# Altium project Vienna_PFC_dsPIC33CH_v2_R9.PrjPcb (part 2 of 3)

## Sheet Vienna_PFC_GateDriver.SchDoc
size D; DocumentNumber: 4; SheetNumber: 4; SheetTotal: 11
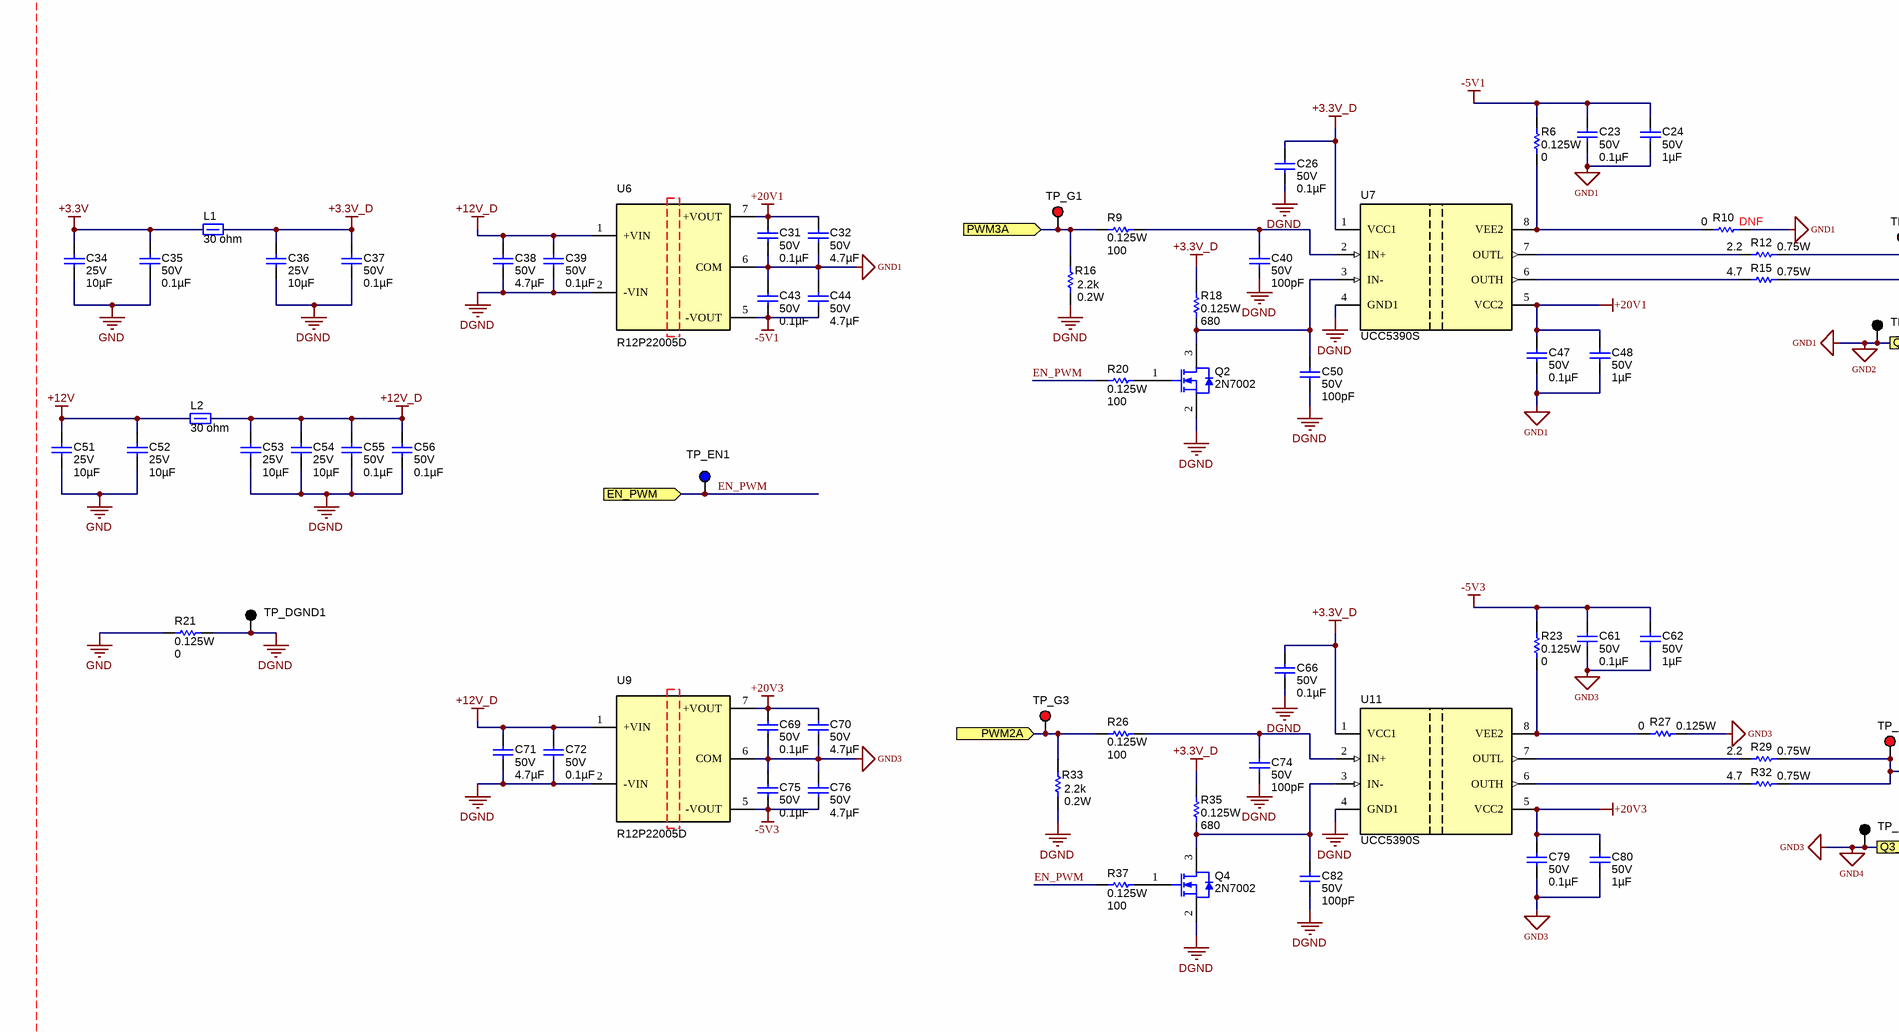
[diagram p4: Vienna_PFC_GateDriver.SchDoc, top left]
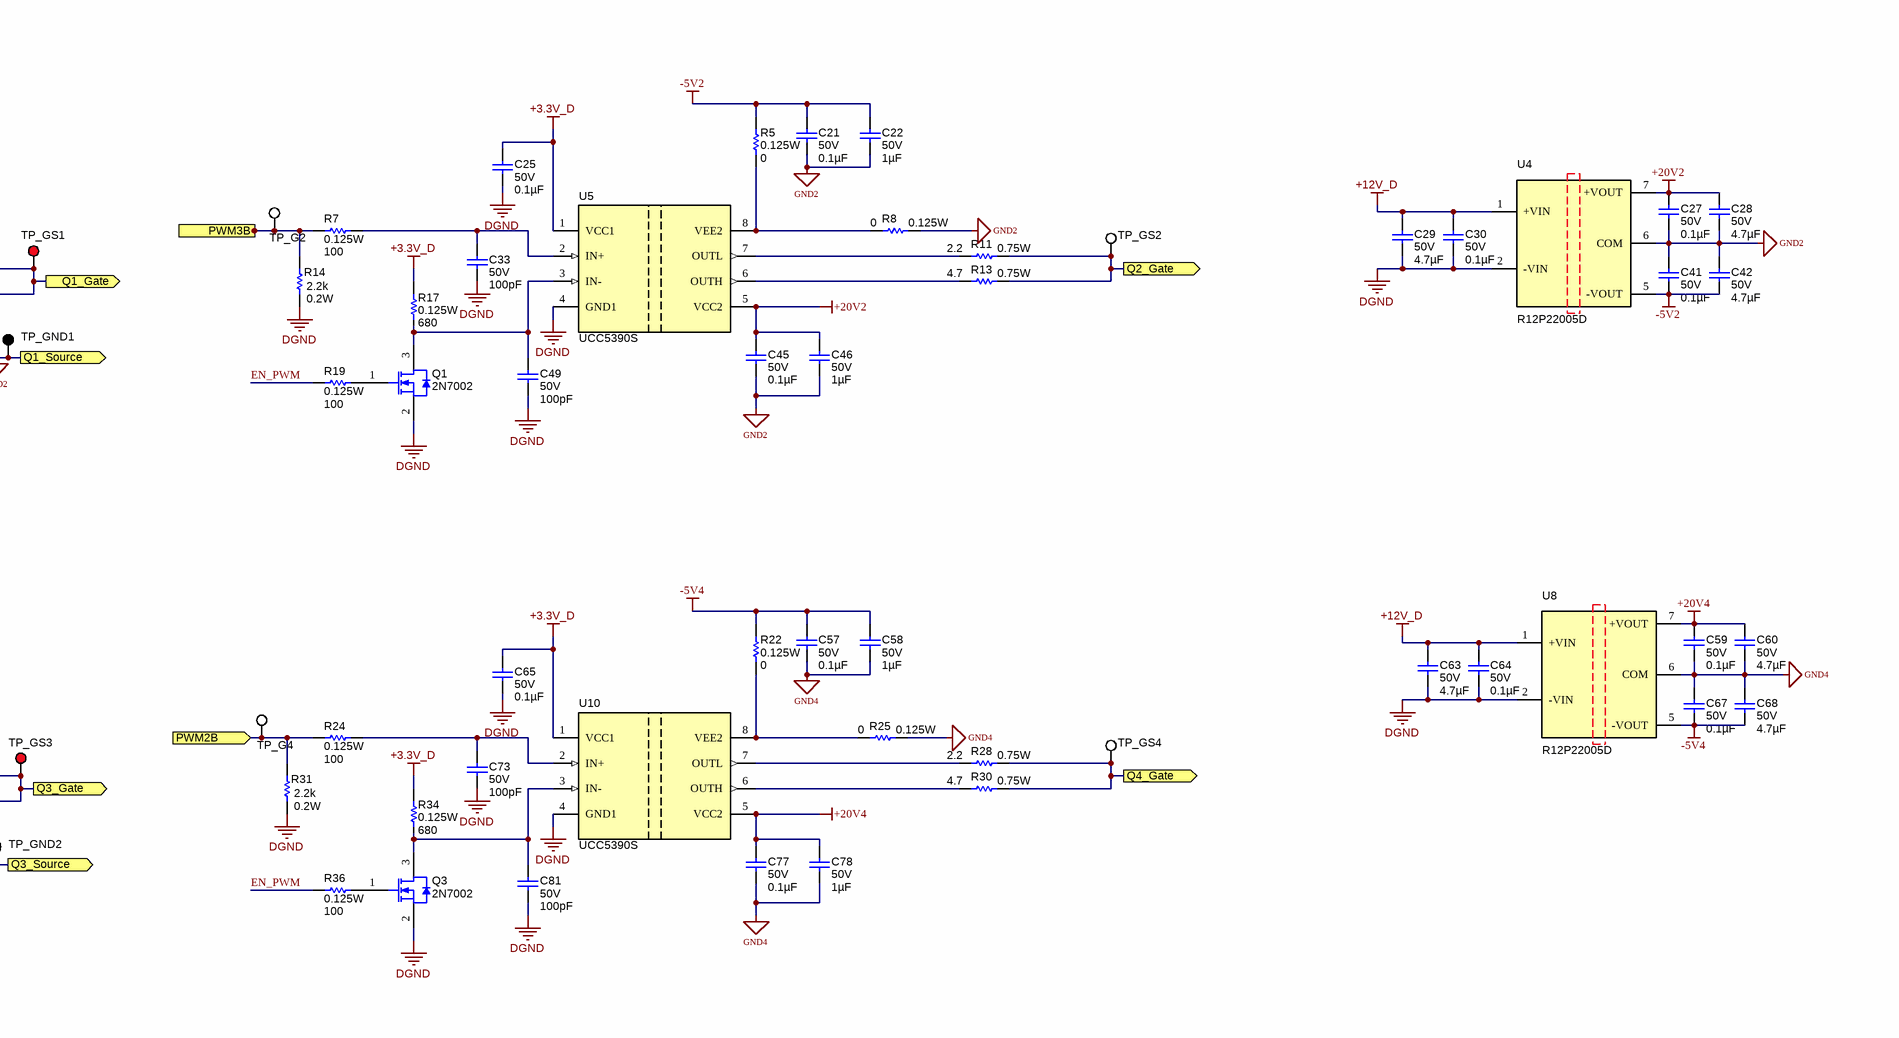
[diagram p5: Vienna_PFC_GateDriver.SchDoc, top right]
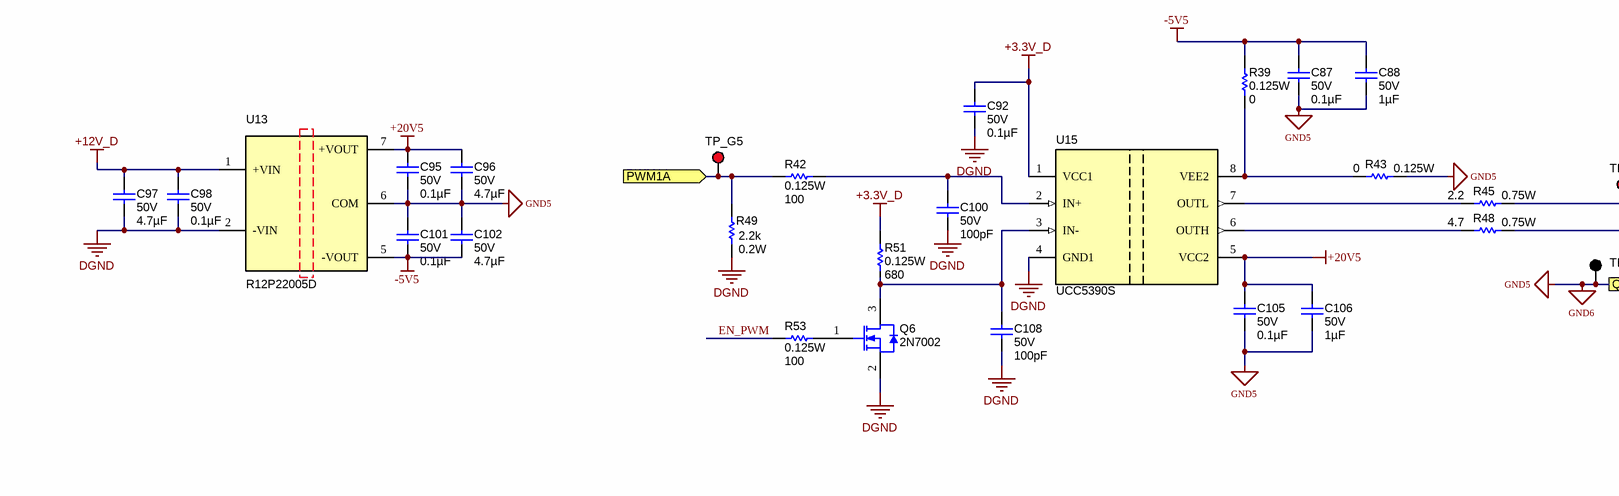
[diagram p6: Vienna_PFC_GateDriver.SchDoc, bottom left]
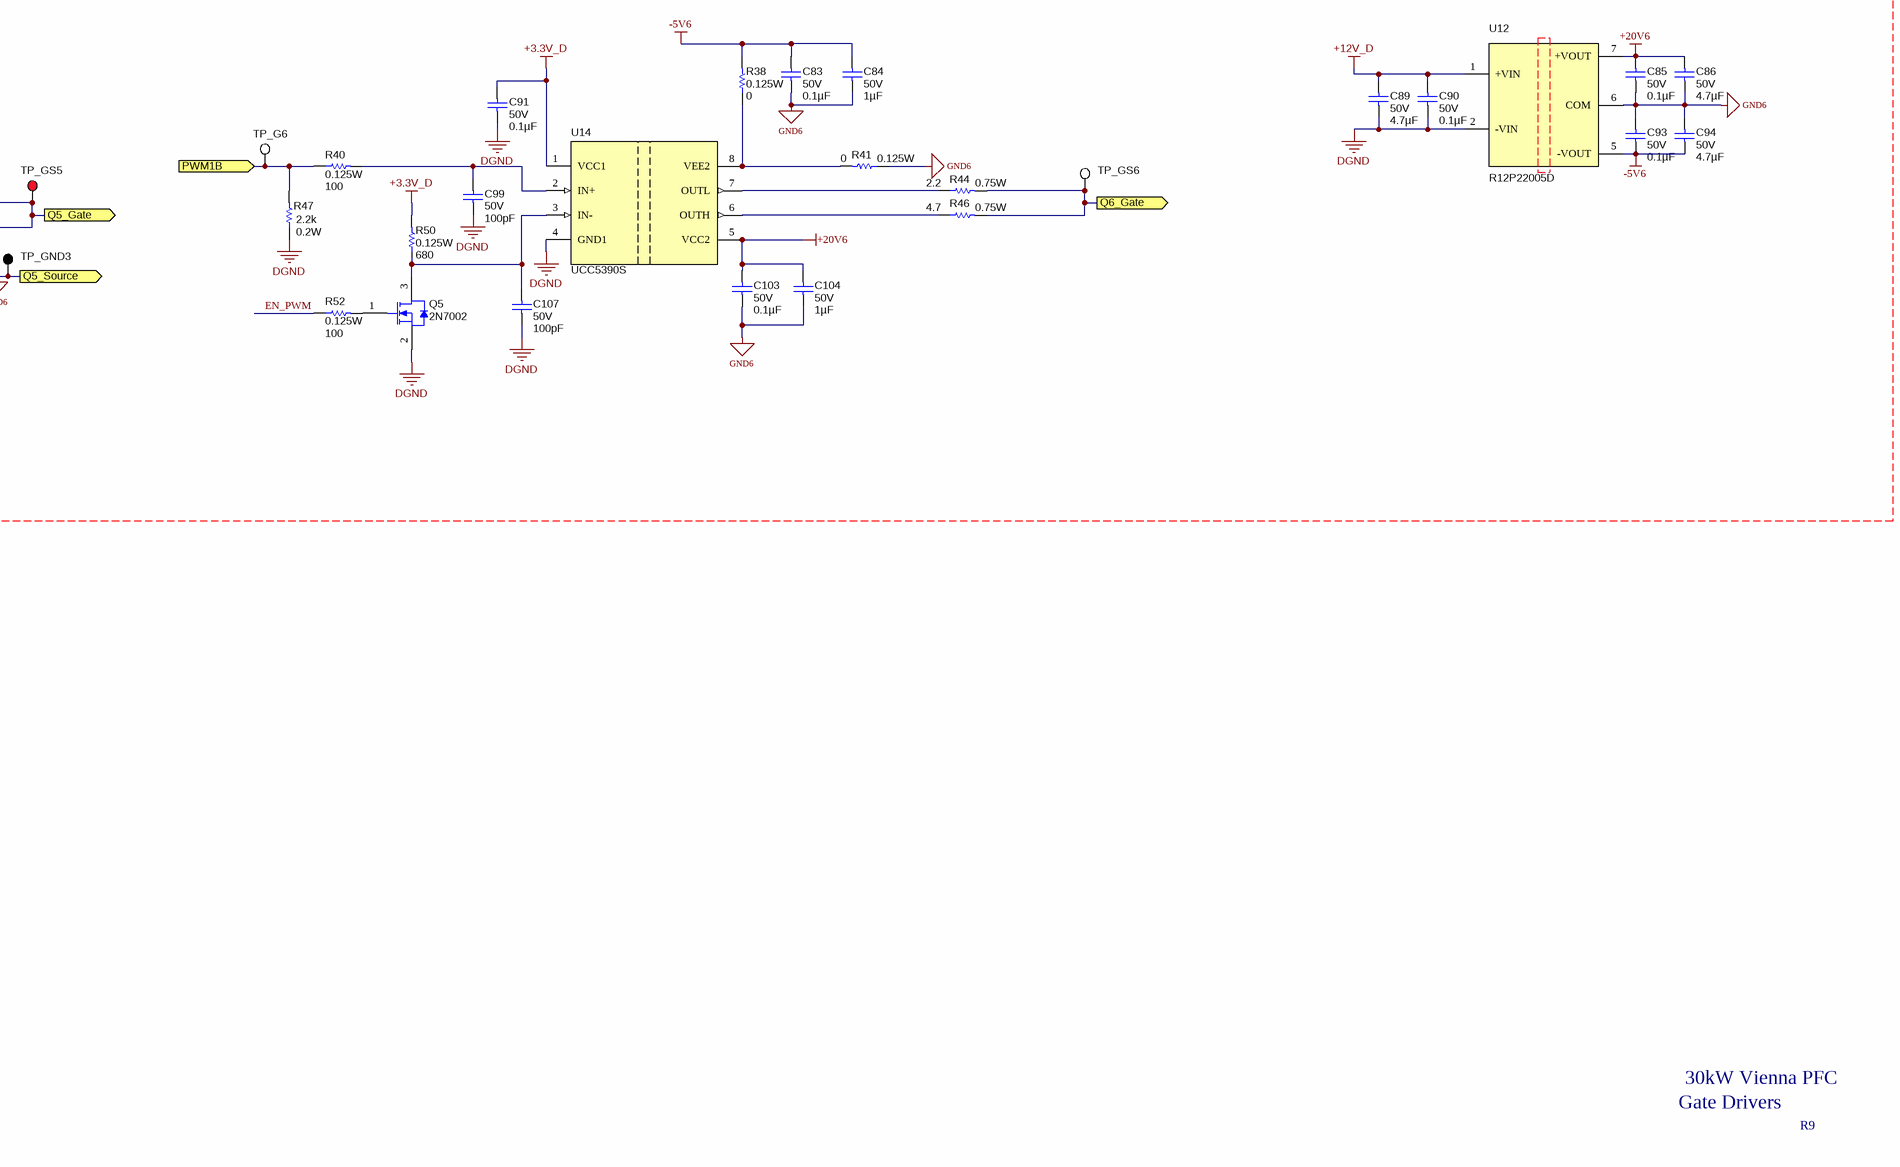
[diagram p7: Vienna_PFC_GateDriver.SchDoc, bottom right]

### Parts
(Parts that share a designator on the sheet are numbered #1, #2 ... from top to bottom, then left to right.)
?#5  (no value)  (graphical)
C21  VDC_V: 50V  ValueDisplayed: 0.1µF  [0805_HV]  (hidden comment: C0805C104J5RACTU)
C22  VDC_V: 50V  ValueDisplayed: 1µF  [0805_HV]  (hidden comment: C0805C105K5RACTU)
C23  VDC_V: 50V  ValueDisplayed: 0.1µF  [0805_HV]  (hidden comment: C0805C104J5RACTU)
C24  VDC_V: 50V  ValueDisplayed: 1µF  [0805_HV]  (hidden comment: C0805C105K5RACTU)
C25  VDC_V: 50V  ValueDisplayed: 0.1µF  [0805_HV]  (hidden comment: C0805C104J5RACTU)
C26  VDC_V: 50V  ValueDisplayed: 0.1µF  [0805_HV]  (hidden comment: C0805C104J5RACTU)
C27  VDC_V: 50V  ValueDisplayed: 0.1µF  [0805_HV]  (hidden comment: C0805C104J5RACTU)
C28  VDC_V: 50V  ValueDisplayed: 4.7µF  [0805_HV]  (hidden comment: C2012X5R1H475K125AB)
C29  VDC_V: 50V  ValueDisplayed: 4.7µF  [0805_HV]  (hidden comment: C2012X5R1H475K125AB)
C30  VDC_V: 50V  ValueDisplayed: 0.1µF  [0805_HV]  (hidden comment: C0805C104J5RACTU)
C31  VDC_V: 50V  ValueDisplayed: 0.1µF  [0805_HV]  (hidden comment: C0805C104J5RACTU)
C32  VDC_V: 50V  ValueDisplayed: 4.7µF  [0805_HV]  (hidden comment: C2012X5R1H475K125AB)
C33  VDC_V: 50V  ValueDisplayed: 100pF  [0805_HV]  (hidden comment: C0805C101J5RACTU)
C34  VDC_V: 25V  ValueDisplayed: 10µF  [1206_190]  (hidden comment: C1206C106K3RACAUTO)
C35  VDC_V: 50V  ValueDisplayed: 0.1µF  [0805_HV]  (hidden comment: C0805C104J5RACTU)
C36  VDC_V: 25V  ValueDisplayed: 10µF  [1206_190]  (hidden comment: C1206C106K3RACAUTO)
C37  VDC_V: 50V  ValueDisplayed: 0.1µF  [0805_HV]  (hidden comment: C0805C104J5RACTU)
C38  VDC_V: 50V  ValueDisplayed: 4.7µF  [0805_HV]  (hidden comment: C2012X5R1H475K125AB)
C39  VDC_V: 50V  ValueDisplayed: 0.1µF  [0805_HV]  (hidden comment: C0805C104J5RACTU)
C40  VDC_V: 50V  ValueDisplayed: 100pF  [0805_HV]  (hidden comment: C0805C101J5RACTU)
C41  VDC_V: 50V  ValueDisplayed: 0.1µF  [0805_HV]  (hidden comment: C0805C104J5RACTU)
C42  VDC_V: 50V  ValueDisplayed: 4.7µF  [0805_HV]  (hidden comment: C2012X5R1H475K125AB)
C43  VDC_V: 50V  ValueDisplayed: 0.1µF  [0805_HV]  (hidden comment: C0805C104J5RACTU)
C44  VDC_V: 50V  ValueDisplayed: 4.7µF  [0805_HV]  (hidden comment: C2012X5R1H475K125AB)
C45  VDC_V: 50V  ValueDisplayed: 0.1µF  [0805_HV]  (hidden comment: C0805C104J5RACTU)
C46  VDC_V: 50V  ValueDisplayed: 1µF  [0805_HV]  (hidden comment: C0805C105K5RACTU)
C47  VDC_V: 50V  ValueDisplayed: 0.1µF  [0805_HV]  (hidden comment: C0805C104J5RACTU)
C48  VDC_V: 50V  ValueDisplayed: 1µF  [0805_HV]  (hidden comment: C0805C105K5RACTU)
C49  VDC_V: 50V  ValueDisplayed: 100pF  [0805_HV]  (hidden comment: C0805C101J5RACTU)
C50  VDC_V: 50V  ValueDisplayed: 100pF  [0805_HV]  (hidden comment: C0805C101J5RACTU)
C51  VDC_V: 25V  ValueDisplayed: 10µF  [1206_190]  (hidden comment: C1206C106K3RACAUTO)
C52  VDC_V: 25V  ValueDisplayed: 10µF  [1206_190]  (hidden comment: C1206C106K3RACAUTO)
C53  VDC_V: 25V  ValueDisplayed: 10µF  [1206_190]  (hidden comment: C1206C106K3RACAUTO)
C54  VDC_V: 25V  ValueDisplayed: 10µF  [1206_190]  (hidden comment: C1206C106K3RACAUTO)
C55  VDC_V: 50V  ValueDisplayed: 0.1µF  [0805_HV]  (hidden comment: C0805C104J5RACTU)
C56  VDC_V: 50V  ValueDisplayed: 0.1µF  [0805_HV]  (hidden comment: C0805C104J5RACTU)
C57  VDC_V: 50V  ValueDisplayed: 0.1µF  [0805_HV]  (hidden comment: C0805C104J5RACTU)
C58  VDC_V: 50V  ValueDisplayed: 1µF  [0805_HV]  (hidden comment: C0805C105K5RACTU)
C59  VDC_V: 50V  ValueDisplayed: 0.1µF  [0805_HV]  (hidden comment: C0805C104J5RACTU)
C60  VDC_V: 50V  ValueDisplayed: 4.7µF  [0805_HV]  (hidden comment: C2012X5R1H475K125AB)
C61  VDC_V: 50V  ValueDisplayed: 0.1µF  [0805_HV]  (hidden comment: C0805C104J5RACTU)
C62  VDC_V: 50V  ValueDisplayed: 1µF  [0805_HV]  (hidden comment: C0805C105K5RACTU)
C63  VDC_V: 50V  ValueDisplayed: 4.7µF  [0805_HV]  (hidden comment: C2012X5R1H475K125AB)
C64  VDC_V: 50V  ValueDisplayed: 0.1µF  [0805_HV]  (hidden comment: C0805C104J5RACTU)
C65  VDC_V: 50V  ValueDisplayed: 0.1µF  [0805_HV]  (hidden comment: C0805C104J5RACTU)
C66  VDC_V: 50V  ValueDisplayed: 0.1µF  [0805_HV]  (hidden comment: C0805C104J5RACTU)
C67  VDC_V: 50V  ValueDisplayed: 0.1µF  [0805_HV]  (hidden comment: C0805C104J5RACTU)
C68  VDC_V: 50V  ValueDisplayed: 4.7µF  [0805_HV]  (hidden comment: C2012X5R1H475K125AB)
C69  VDC_V: 50V  ValueDisplayed: 0.1µF  [0805_HV]  (hidden comment: C0805C104J5RACTU)
C70  VDC_V: 50V  ValueDisplayed: 4.7µF  [0805_HV]  (hidden comment: C2012X5R1H475K125AB)
C71  VDC_V: 50V  ValueDisplayed: 4.7µF  [0805_HV]  (hidden comment: C2012X5R1H475K125AB)
C72  VDC_V: 50V  ValueDisplayed: 0.1µF  [0805_HV]  (hidden comment: C0805C104J5RACTU)
C73  VDC_V: 50V  ValueDisplayed: 100pF  [0805_HV]  (hidden comment: C0805C101J5RACTU)
C74  VDC_V: 50V  ValueDisplayed: 100pF  [0805_HV]  (hidden comment: C0805C101J5RACTU)
C75  VDC_V: 50V  ValueDisplayed: 0.1µF  [0805_HV]  (hidden comment: C0805C104J5RACTU)
C76  VDC_V: 50V  ValueDisplayed: 4.7µF  [0805_HV]  (hidden comment: C2012X5R1H475K125AB)
C77  VDC_V: 50V  ValueDisplayed: 0.1µF  [0805_HV]  (hidden comment: C0805C104J5RACTU)
C78  VDC_V: 50V  ValueDisplayed: 1µF  [0805_HV]  (hidden comment: C0805C105K5RACTU)
C79  VDC_V: 50V  ValueDisplayed: 0.1µF  [0805_HV]  (hidden comment: C0805C104J5RACTU)
C80  VDC_V: 50V  ValueDisplayed: 1µF  [0805_HV]  (hidden comment: C0805C105K5RACTU)
C81  VDC_V: 50V  ValueDisplayed: 100pF  [0805_HV]  (hidden comment: C0805C101J5RACTU)
C82  VDC_V: 50V  ValueDisplayed: 100pF  [0805_HV]  (hidden comment: C0805C101J5RACTU)
C83  VDC_V: 50V  ValueDisplayed: 0.1µF  [0805_HV]  (hidden comment: C0805C104J5RACTU)
C84  VDC_V: 50V  ValueDisplayed: 1µF  [0805_HV]  (hidden comment: C0805C105K5RACTU)
C85  VDC_V: 50V  ValueDisplayed: 0.1µF  [0805_HV]  (hidden comment: C0805C104J5RACTU)
C86  VDC_V: 50V  ValueDisplayed: 4.7µF  [0805_HV]  (hidden comment: C2012X5R1H475K125AB)
C87  VDC_V: 50V  ValueDisplayed: 0.1µF  [0805_HV]  (hidden comment: C0805C104J5RACTU)
C88  VDC_V: 50V  ValueDisplayed: 1µF  [0805_HV]  (hidden comment: C0805C105K5RACTU)
C89  VDC_V: 50V  ValueDisplayed: 4.7µF  [0805_HV]  (hidden comment: C2012X5R1H475K125AB)
C90  VDC_V: 50V  ValueDisplayed: 0.1µF  [0805_HV]  (hidden comment: C0805C104J5RACTU)
C91  VDC_V: 50V  ValueDisplayed: 0.1µF  [0805_HV]  (hidden comment: C0805C104J5RACTU)
C92  VDC_V: 50V  ValueDisplayed: 0.1µF  [0805_HV]  (hidden comment: C0805C104J5RACTU)
C93  VDC_V: 50V  ValueDisplayed: 0.1µF  [0805_HV]  (hidden comment: C0805C104J5RACTU)
C94  VDC_V: 50V  ValueDisplayed: 4.7µF  [0805_HV]  (hidden comment: C2012X5R1H475K125AB)
C95  VDC_V: 50V  ValueDisplayed: 0.1µF  [0805_HV]  (hidden comment: C0805C104J5RACTU)
C96  VDC_V: 50V  ValueDisplayed: 4.7µF  [0805_HV]  (hidden comment: C2012X5R1H475K125AB)
C97  VDC_V: 50V  ValueDisplayed: 4.7µF  [0805_HV]  (hidden comment: C2012X5R1H475K125AB)
C98  VDC_V: 50V  ValueDisplayed: 0.1µF  [0805_HV]  (hidden comment: C0805C104J5RACTU)
C99  VDC_V: 50V  ValueDisplayed: 100pF  [0805_HV]  (hidden comment: C0805C101J5RACTU)
C100  VDC_V: 50V  ValueDisplayed: 100pF  [0805_HV]  (hidden comment: C0805C101J5RACTU)
C101  VDC_V: 50V  ValueDisplayed: 0.1µF  [0805_HV]  (hidden comment: C0805C104J5RACTU)
C102  VDC_V: 50V  ValueDisplayed: 4.7µF  [0805_HV]  (hidden comment: C2012X5R1H475K125AB)
C103  VDC_V: 50V  ValueDisplayed: 0.1µF  [0805_HV]  (hidden comment: C0805C104J5RACTU)
C104  VDC_V: 50V  ValueDisplayed: 1µF  [0805_HV]  (hidden comment: C0805C105K5RACTU)
C105  VDC_V: 50V  ValueDisplayed: 0.1µF  [0805_HV]  (hidden comment: C0805C104J5RACTU)
C106  VDC_V: 50V  ValueDisplayed: 1µF  [0805_HV]  (hidden comment: C0805C105K5RACTU)
C107  VDC_V: 50V  ValueDisplayed: 100pF  [0805_HV]  (hidden comment: C0805C101J5RACTU)
C108  VDC_V: 50V  ValueDisplayed: 100pF  [0805_HV]  (hidden comment: C0805C101J5RACTU)
L1  value 30 ohm  [0805_HV]  (hidden comment: MPZ2012S300AT000)
L2  value 30 ohm  [0805_HV]  (hidden comment: MPZ2012S300AT000)
Q1  2N7002  [SOT-23]
Q2  2N7002  [SOT-23]
Q3  2N7002  [SOT-23]
Q4  2N7002  [SOT-23]
Q5  2N7002  [SOT-23]
Q6  2N7002  [SOT-23]
R5  Value2: 0.125W  ValueDisplayed: 0  [0805_HV]  (hidden comment: CRCW08050000Z0EA)
R6  Value2: 0.125W  ValueDisplayed: 0  [0805_HV]  (hidden comment: CRCW08050000Z0EA)
R7  Value2: 0.125W  ValueDisplayed: 100  [0805_HV]  (hidden comment: CRCW0805100RFKEAC)
R8  Value2: 0.125W  ValueDisplayed: 0  [0805_HV]  (hidden comment: CRCW08050000Z0EA)
R9  Value2: 0.125W  ValueDisplayed: 100  [0805_HV]  (hidden comment: CRCW0805100RFKEAC)
R10  Value2: DNF  ValueDisplayed: 0  [0805_HV]  (hidden comment: CRCW08050000Z0EA)
R11  Value2: 0.75W  ValueDisplayed: 2.2  [1206_190]  (hidden comment: CRCW12064R70FKEAHP)
R12  Value2: 0.75W  ValueDisplayed: 2.2  [1206_190]  (hidden comment: CRCW12064R70FKEAHP)
R13  Value2: 0.75W  ValueDisplayed: 4.7  [1206_190]  (hidden comment: CRCW12062R20FKEAHP)
R14  value 2.2k  Power_W: 0.2W  [0805_HV]  (hidden comment: TNPW08052K20BEEA)
R15  Value2: 0.75W  ValueDisplayed: 4.7  [1206_190]  (hidden comment: CRCW12062R20FKEAHP)
R16  value 2.2k  Power_W: 0.2W  [0805_HV]  (hidden comment: TNPW08052K20BEEA)
R17  Value2: 0.125W  ValueDisplayed: 680  [0805_HV]  (hidden comment: CRCW0805680RFKEA)
R18  Value2: 0.125W  ValueDisplayed: 680  [0805_HV]  (hidden comment: CRCW0805680RFKEA)
R19  Value2: 0.125W  ValueDisplayed: 100  [0805_HV]  (hidden comment: CRCW0805100RFKEAC)
R20  Value2: 0.125W  ValueDisplayed: 100  [0805_HV]  (hidden comment: CRCW0805100RFKEAC)
R21  Value2: 0.125W  ValueDisplayed: 0  [0805_HV]  (hidden comment: CRCW08050000Z0EA)
R22  Value2: 0.125W  ValueDisplayed: 0  [0805_HV]  (hidden comment: CRCW08050000Z0EA)
R23  Value2: 0.125W  ValueDisplayed: 0  [0805_HV]  (hidden comment: CRCW08050000Z0EA)
R24  Value2: 0.125W  ValueDisplayed: 100  [0805_HV]  (hidden comment: CRCW0805100RFKEAC)
R25  Value2: 0.125W  ValueDisplayed: 0  [0805_HV]  (hidden comment: CRCW08050000Z0EA)
R26  Value2: 0.125W  ValueDisplayed: 100  [0805_HV]  (hidden comment: CRCW0805100RFKEAC)
R27  Value2: 0.125W  ValueDisplayed: 0  [0805_HV]  (hidden comment: CRCW08050000Z0EA)
R28  Value2: 0.75W  ValueDisplayed: 2.2  [1206_190]  (hidden comment: CRCW12064R70FKEAHP)
R29  Value2: 0.75W  ValueDisplayed: 2.2  [1206_190]  (hidden comment: CRCW12064R70FKEAHP)
R30  Value2: 0.75W  ValueDisplayed: 4.7  [1206_190]  (hidden comment: CRCW12062R20FKEAHP)
R31  value 2.2k  Power_W: 0.2W  [0805_HV]  (hidden comment: TNPW08052K20BEEA)
R32  Value2: 0.75W  ValueDisplayed: 4.7  [1206_190]  (hidden comment: CRCW12062R20FKEAHP)
R33  value 2.2k  Power_W: 0.2W  [0805_HV]  (hidden comment: TNPW08052K20BEEA)
R34  Value2: 0.125W  ValueDisplayed: 680  [0805_HV]  (hidden comment: CRCW0805680RFKEA)
R35  Value2: 0.125W  ValueDisplayed: 680  [0805_HV]  (hidden comment: CRCW0805680RFKEA)
R36  Value2: 0.125W  ValueDisplayed: 100  [0805_HV]  (hidden comment: CRCW0805100RFKEAC)
R37  Value2: 0.125W  ValueDisplayed: 100  [0805_HV]  (hidden comment: CRCW0805100RFKEAC)
R38  Value2: 0.125W  ValueDisplayed: 0  [0805_HV]  (hidden comment: CRCW08050000Z0EA)
R39  Value2: 0.125W  ValueDisplayed: 0  [0805_HV]  (hidden comment: CRCW08050000Z0EA)
R40  Value2: 0.125W  ValueDisplayed: 100  [0805_HV]  (hidden comment: CRCW0805100RFKEAC)
R41  Value2: 0.125W  ValueDisplayed: 0  [0805_HV]  (hidden comment: CRCW08050000Z0EA)
R42  Value2: 0.125W  ValueDisplayed: 100  [0805_HV]  (hidden comment: CRCW0805100RFKEAC)
R43  Value2: 0.125W  ValueDisplayed: 0  [0805_HV]  (hidden comment: CRCW08050000Z0EA)
R44  Value2: 0.75W  ValueDisplayed: 2.2  [1206_190]  (hidden comment: CRCW12064R70FKEAHP)
R45  Value2: 0.75W  ValueDisplayed: 2.2  [1206_190]  (hidden comment: CRCW12064R70FKEAHP)
R46  Value2: 0.75W  ValueDisplayed: 4.7  [1206_190]  (hidden comment: CRCW12062R20FKEAHP)
R47  value 2.2k  Power_W: 0.2W  [0805_HV]  (hidden comment: TNPW08052K20BEEA)
R48  Value2: 0.75W  ValueDisplayed: 4.7  [1206_190]  (hidden comment: CRCW12062R20FKEAHP)
R49  value 2.2k  Power_W: 0.2W  [0805_HV]  (hidden comment: TNPW08052K20BEEA)
R50  Value2: 0.125W  ValueDisplayed: 680  [0805_HV]  (hidden comment: CRCW0805680RFKEA)
R51  Value2: 0.125W  ValueDisplayed: 680  [0805_HV]  (hidden comment: CRCW0805680RFKEA)
R52  Value2: 0.125W  ValueDisplayed: 100  [0805_HV]  (hidden comment: CRCW0805100RFKEAC)
R53  Value2: 0.125W  ValueDisplayed: 100  [0805_HV]  (hidden comment: CRCW0805100RFKEAC)
TP_DGND1  5011  [Keystone5011]  (value not drawn)
TP_EN1  5127  [Keystone5127]  (value not drawn)
TP_G1  5010  [Keystone5010]  (value not drawn)
TP_G2  5012  [Keystone5012]  (value not drawn)
TP_G3  5010  [Keystone5010]  (value not drawn)
TP_G4  5012  [Keystone5012]  (value not drawn)
TP_G5  5010  [Keystone5010]  (value not drawn)
TP_G6  5012  [Keystone5012]  (value not drawn)
TP_GND1  5011  [Keystone5011]  (value not drawn)
TP_GND2  5011  [Keystone5011]  (value not drawn)
TP_GND3  5011  [Keystone5011]  (value not drawn)
TP_GS1  5010  [Keystone5010]  (value not drawn)
TP_GS2  5012  [Keystone5012]  (value not drawn)
TP_GS3  5010  [Keystone5010]  (value not drawn)
TP_GS4  5012  [Keystone5012]  (value not drawn)
TP_GS5  5010  [Keystone5010]  (value not drawn)
TP_GS6  5012  [Keystone5012]  (value not drawn)
U4  R12P22005D  [R12P22005D]
U5  UCC5390S  [UCC5390S]
U6  R12P22005D  [R12P22005D]
U7  UCC5390S  [UCC5390S]
U8  R12P22005D  [R12P22005D]
U9  R12P22005D  [R12P22005D]
U10  UCC5390S  [UCC5390S]
U11  UCC5390S  [UCC5390S]
U12  R12P22005D  [R12P22005D]
U13  R12P22005D  [R12P22005D]
U14  UCC5390S  [UCC5390S]
U15  UCC5390S  [UCC5390S]

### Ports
EN_PWM (in), PWM1A (in), PWM1B (in), PWM2A (in), PWM2B (in), PWM3A (in), PWM3B (in), Q1_Gate (out), Q1_Source (out), Q2_Gate (out), Q3_Gate (out), Q3_Source (out), Q4_Gate (out), Q5_Gate (out), Q5_Source (out), Q6_Gate (out)

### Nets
+3.3V: C34.1 C35.1 L1.1
+3.3V_D: C25.1 C26.1 C36.1 C37.1 C65.1 C66.1 C91.1 C92.1 L1.2 R17.2 R18.2 R34.2 R35.2 R50.2 R51.2 U5.1(VCC1) U7.1(VCC1) U10.1(VCC1) U11.1(VCC1) U14.1(VCC1) U15.1(VCC1)
+12V: C51.1 C52.1 L2.1
+12V_D: C29.1 C30.1 C38.1 C39.1 C53.1 C54.1 C55.1 C56.1 C63.1 C64.1 C71.1 C72.1 C89.1 C90.1 C97.1 C98.1 L2.2 U4.1(+VIN) U6.1(+VIN) U8.1(+VIN) U9.1(+VIN) U12.1(+VIN) U13.1(+VIN)
+20V1: C31.1 C32.1 C47.1 C48.1 U6.7(+VOUT) U7.5(VCC2)
+20V2: C27.1 C28.1 C45.1 C46.1 U4.7(+VOUT) U5.5(VCC2)
+20V3: C69.1 C70.1 C79.1 C80.1 U9.7(+VOUT) U11.5(VCC2)
+20V4: C59.1 C60.1 C77.1 C78.1 U8.7(+VOUT) U10.5(VCC2)
+20V5: C95.1 C96.1 C105.1 C106.1 U13.7(+VOUT) U15.5(VCC2)
+20V6: C85.1 C86.1 C103.1 C104.1 U12.7(+VOUT) U14.5(VCC2)
-5V1: C23.1 C24.1 C43.2 C44.2 R6.2 U6.5(-VOUT)
-5V2: C21.1 C22.1 C41.2 C42.2 R5.2 U4.5(-VOUT)
-5V3: C61.1 C62.1 C75.2 C76.2 R23.2 U9.5(-VOUT)
-5V4: C57.1 C58.1 C67.2 C68.2 R22.2 U8.5(-VOUT)
-5V5: C87.1 C88.1 C101.2 C102.2 R39.2 U13.5(-VOUT)
-5V6: C83.1 C84.1 C93.2 C94.2 R38.2 U12.5(-VOUT)
DGND: C25.2 C26.2 C29.2 C30.2 C33.2 C36.2 C37.2 C38.2 C39.2 C40.2 C49.2 C50.2 C53.2 C54.2 C55.2 C56.2 C63.2 C64.2 C65.2 C66.2 C71.2 C72.2 C73.2 C74.2 C81.2 C82.2 C89.2 C90.2 C91.2 C92.2 C97.2 C98.2 C99.2 C100.2 C107.2 C108.2 Q1.2(S) Q2.2(S) Q3.2(S) Q4.2(S) Q5.2(S) Q6.2(S) R14.1 R16.1 R21.2 R31.1 R33.1 R47.1 R49.1 TP_DGND1.1 U4.2(-VIN) U5.4(GND1) U6.2(-VIN) U7.4(GND1) U8.2(-VIN) U9.2(-VIN) U10.4(GND1) U11.4(GND1) U12.2(-VIN) U13.2(-VIN) U14.4(GND1) U15.4(GND1)
GND: C34.2 C35.2 C51.2 C52.2 R21.1
GND1: C21.2 C22.2 C23.2 C24.2 C27.2 C28.2 C31.2 C32.2 C41.1 C42.1 C43.1 C44.1 C45.2 C46.2 C47.2 C48.2 R8.1 R10.1 TP_GND1.1 U4.6(COM) U6.6(COM) ; port Q1_Source  [also labelled GND2]
GND3: C57.2 C58.2 C59.2 C60.2 C61.2 C62.2 C67.1 C68.1 C69.2 C70.2 C75.1 C76.1 C77.2 C78.2 C79.2 C80.2 R25.1 R27.1 TP_GND2.1 U8.6(COM) U9.6(COM) ; port Q3_Source  [also labelled GND4]
GND5: C83.2 C84.2 C85.2 C86.2 C87.2 C88.2 C93.1 C94.1 C95.2 C96.2 C101.1 C102.1 C103.2 C104.2 C105.2 C106.2 R41.1 R43.1 TP_GND3.1 U12.6(COM) U13.6(COM) ; port Q5_Source  [also labelled GND6]
EN_PWM: R19.1 R20.1 R36.1 R37.1 R52.1 R53.1 TP_EN1.1 ; port EN_PWM
NetC33_1: C33.1 R7.2 U5.2(IN+)
NetC40_1: C40.1 R9.2 U7.2(IN+)
NetC49_1: C49.1 Q1.3(D) R17.1 U5.3(IN-)
NetC50_1: C50.1 Q2.3(D) R18.1 U7.3(IN-)
NetC73_1: C73.1 R24.2 U10.2(IN+)
NetC74_1: C74.1 R26.2 U11.2(IN+)
NetC81_1: C81.1 Q3.3(D) R34.1 U10.3(IN-)
NetC82_1: C82.1 Q4.3(D) R35.1 U11.3(IN-)
NetC99_1: C99.1 R40.2 U14.2(IN+)
NetC100_1: C100.1 R42.2 U15.2(IN+)
NetC107_1: C107.1 Q5.3(D) R50.1 U14.3(IN-)
NetC108_1: C108.1 Q6.3(D) R51.1 U15.3(IN-)
NetJ5_37: R9.1 R16.2 TP_G1.1 ; port PWM3A
NetJ5_40: R24.1 R31.2 TP_G4.1 ; port PWM2B
NetJ5_41: R7.1 R14.2 TP_G2.1 ; port PWM3B
NetJ5_42: R26.1 R33.2 TP_G3.1 ; port PWM2A
NetJ5_45: R42.1 R49.2 TP_G5.1 ; port PWM1A
NetJ5_47: R40.1 R47.2 TP_G6.1 ; port PWM1B
NetQ1_1: Q1.1(G) R19.2
NetQ2_1: Q2.1(G) R20.2
NetQ3_1: Q3.1(G) R36.2
NetQ4_1: Q4.1(G) R37.2
NetQ5_1: Q5.1(G) R52.2
NetQ6_1: Q6.1(G) R53.2
NetR5_1: R5.1 R8.2 U5.8(VEE2)
NetR6_1: R6.1 R10.2 U7.8(VEE2)
NetR11_1: R11.1 U5.7(OUTL)
NetR11_2: R11.2 R13.2 TP_GS2.1 ; port Q2_Gate
NetR12_1: R12.1 U7.7(OUTL)
NetR12_2: R12.2 R15.2 TP_GS1.1 ; port Q1_Gate
NetR13_1: R13.1 U5.6(OUTH)
NetR15_1: R15.1 U7.6(OUTH)
NetR22_1: R22.1 R25.2 U10.8(VEE2)
NetR23_1: R23.1 R27.2 U11.8(VEE2)
NetR28_1: R28.1 U10.7(OUTL)
NetR28_2: R28.2 R30.2 TP_GS4.1 ; port Q4_Gate
NetR29_1: R29.1 U11.7(OUTL)
NetR29_2: R29.2 R32.2 TP_GS3.1 ; port Q3_Gate
NetR30_1: R30.1 U10.6(OUTH)
NetR32_1: R32.1 U11.6(OUTH)
NetR38_1: R38.1 R41.2 U14.8(VEE2)
NetR39_1: R39.1 R43.2 U15.8(VEE2)
NetR44_1: R44.1 U14.7(OUTL)
NetR44_2: R44.2 R46.2 TP_GS6.1 ; port Q6_Gate
NetR45_1: R45.1 U15.7(OUTL)
NetR45_2: R45.2 R48.2 TP_GS5.1 ; port Q5_Gate
NetR46_1: R46.1 U14.6(OUTH)
NetR48_1: R48.1 U15.6(OUTH)

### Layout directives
net class GateDriver: +3.3V, +3.3V_D, +12V, +12V_D, +20V1, +20V2, +20V3, +20V4, +20V5, +20V6, -5V1, -5V2, -5V3, -5V4, -5V5, -5V6, DGND, EN_PWM, GND, GND1, GND2, GND3, GND4, GND5, GND6

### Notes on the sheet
- 30kW Vienna PFC
- Gate Drivers
- R9

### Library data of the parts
?#5 = Title Block D
C21 C23 C25-C27 C30 C31 C35 C37 C39 C41 C43 C45 C47 C55-C57 C59 C61 C64-C67 C69 C72 C75 C77 C79 C83 C85 C87 C90-C93 C95 C98 C101 C103 C105 = C0805C104J5RACTU: CAP, CERM, 0.1 µF, 50 V, +/- 5%, X7R, 0805; Manufacturer: Kemet; CompType: Capacitor; Tolerance_%: 5; TaMin_C: -55; TaMax_C: 125; Cap_Case: 0805; AEC Category: Q200
C22 C24 C46 C48 C58 C62 C78 C80 C84 C88 C104 C106 = C0805C105K5RACTU: CAP, CERM, 1 µF, 50 V, +/- 5%, X7R, 0805; Manufacturer: Kemet; CompType: Capacitor; Tolerance_%: 10; TaMin_C: -55; TaMax_C: 125; Cap_Case: 0805; AEC Category: Q200
C28 C29 C32 C38 C42 C44 C60 C63 C68 C70 C71 C76 C86 C89 C94 C96 C97 C102 = C2012X5R1H475K125AB: CAP, CERM, 4.7 µF, 50 V, +/- 10%, X5R, 0805; Manufacturer: TDK; Polarized: N; CompType: Capacitor; Value: 4.7uF; U/M: EA; Cap_F: 0.0000047; Tolerance_%: 10; Value1: Unknown; TaMin_C: -55; TaMax_C: 85; Cap_Case: 0805; AEC Category: Q200
C33 C40 C49 C50 C73 C74 C81 C82 C99 C100 C107 C108 = C0805C101J5RACTU: CAP, CERM, 100 pF, 50 V, +/- 5%, X7R, 0805; Manufacturer: Kemet; CompType: Capacitor; Tolerance_%: 5; TaMin_C: -55; TaMax_C: 125; Cap_Case: 0805; AEC Category: Q200
C34 C36 C51-C54 = C1206C106K3RACAUTO: CAP, CERM, 10 µF, 25 V, +/- 10%, X7R, 1206_190; Manufacturer: Kemet; Polarized: N; CompType: Capacitor; Value: 10uF; U/M: EA; Cap_F: 0.00001; Tolerance_%: 10; Value1: Unknown; TaMin_C: -55; TaMax_C: 125; Cap_Case: 1206; AEC Category: Q200
L1 L2 = MPZ2012S300AT000: Ferrite Bead, 30 ohm @ 100 MHz, 6 A, 0805; Manufacturer: TDK; Imax_A: 6; DCR_ohm: 0.01; Value1: 0.01 ohm; Value2: 6A; ZTyp@100MHz_Ohm: 30
Q1-Q6 = 2N7002: MOSFET, N-CH, 60 V, 115 MA, SOT-23; Manufacturer: Fairchild Semiconductor; Alternate Manufacturer: None; U/M: EA; ChType: N; Value: 60V; VdsMax_V: 60; Value1: ? ohm; Value2: ? nC; Vgs_V: 20; IdsMax_A: 115; SizeAreaWB_mm2: 14; SizeArea_mm2: 7.5; SizeX_mm: 2.5; SizeY_mm: 3; SizeZ_mm: 1.1; AEC Category: Q101
R5 R6 R8 R10 R21-R23 R25 R27 R38 R39 R41 R43 = CRCW08050000Z0EA: RES, 0, 5%, 0.125 W, 0805; Manufacturer: Vishay-Dale; CompType: Resistor; Value: 0; Tolerance_%: 5; Power_W: 0.125; VDC_V: 150; TempCo: 200 ppm/C; EIA_Code: E24; U/M: EA; AEC Category: Q200
R7 R9 R19 R20 R24 R26 R36 R37 R40 R42 R52 R53 = CRCW0805100RFKEAC: RES, 100, 1%, 0.125 W, 0805; Manufacturer: Vishay-Dale; CompType: Resistor; Value: 348; Value_Code: 100R; Tolerance_%: 1; Power_W: 0.125; VDC_V: 150; TempCo: 100 ppm/C; EIA_Code: E96; U/M: EA; AEC Category: Q200
R11 R12 R28 R29 R44 R45 = CRCW12062R20FKEAHP: RES, 2.2, 1%, 0.75 W, 1206; Manufacturer: Vishay-Dale; CompType: Resistor; Value: 2.2; Value_Code: 2R2; Tolerance_%: 1; Power_W: 0.75; VDC_V: 200V; TempCo: 100 ppm/C; U/M: EA; AEC Category: Q200
R13 R15 R30 R32 R46 R48 = CRCW12064R70FKEAHP: RES, 4.7, 1%, 0.75 W, 1206; Manufacturer: Vishay-Dale; CompType: Resistor; Value: 4.7; Value_Code: 4R7; Tolerance_%: 1; Power_W: 0.75; VDC_V: 200V; TempCo: 100 ppm/C; U/M: EA; AEC Category: Q200
R14 R16 R31 R33 R47 R49 = TNPW08052K20BEEA: RES 2.2K OHM 0.1% 1/5W 0805; Manufacturer: Vishay; CompType: Resistor; Tolerance_%: 0.1; VDC_V: 200V; TempCo: 25ppm/C; AEC Category: Q200
R17 R18 R34 R35 R50 R51 = CRCW0805680RFKEA: RES, 680, 1%, 0.125 W, 0805; Manufacturer: Vishay-Dale; CompType: Resistor; Value: 680; Res_ohm: 348; Value_Code: 680R; Tolerance_%: 1; Power_W: 0.125; VDC_V: 150; TempCo: 100 ppm/C; EIA_Code: E96; U/M: EA; AEC Category: Q200
TP_DGND1 TP_GND1-TP_GND3 = 5011: Test Point, Multipurpose, Black, TH; Manufacturer: Keystone; CompType: Test Point Loop; ContactFinish: Silver
TP_EN1 = 5127: Test Point, Multipurpose, Blue, TH; Manufacturer: Keystone; CompType: Test Point Loop; U/M: EA; ContactFinish: Silver
TP_G1 TP_G3 TP_G5 TP_GS1 TP_GS3 TP_GS5 = 5010: Test Point, Multipurpose, Red, TH; Manufacturer: Keystone; CompType: Test Point Loop; ContactFinish: Silver
TP_G2 TP_G4 TP_G6 TP_GS2 TP_GS4 TP_GS6 = 5012: Test Point, Multipurpose, White, TH; Manufacturer: Keystone; CompType: Test Point Loop; ContactFinish: Silver
U4 U6 U8 U9 U12 U13 = R12P22005D: CONV DC/DC 2W 12VIN +20/-5VOUT T; Manufacturer: Recom Power; CompType: DC DC Converters
U5 U7 U10 U11 U14 U15 = UCC5390S: Isolated Gate Drivers with High CMTI and Scalable Drive Strength, D0008B (SOIC-8); Manufacturer: Texas Instruments; SymbolCreator: a0411947; SizeArea_mm2: 29.4; SizeAreaWB_mm2: 55.2; SizeX_mm: 6; SizeY_mm: 4.9; SizeZ_mm: 1.75; CompType: IC; U/M: EA

## Sheet Vienna_PFC_OutputVoltageSensor.SchDoc
size C; DocumentNumber: 7; SheetNumber: 7; SheetTotal: 11
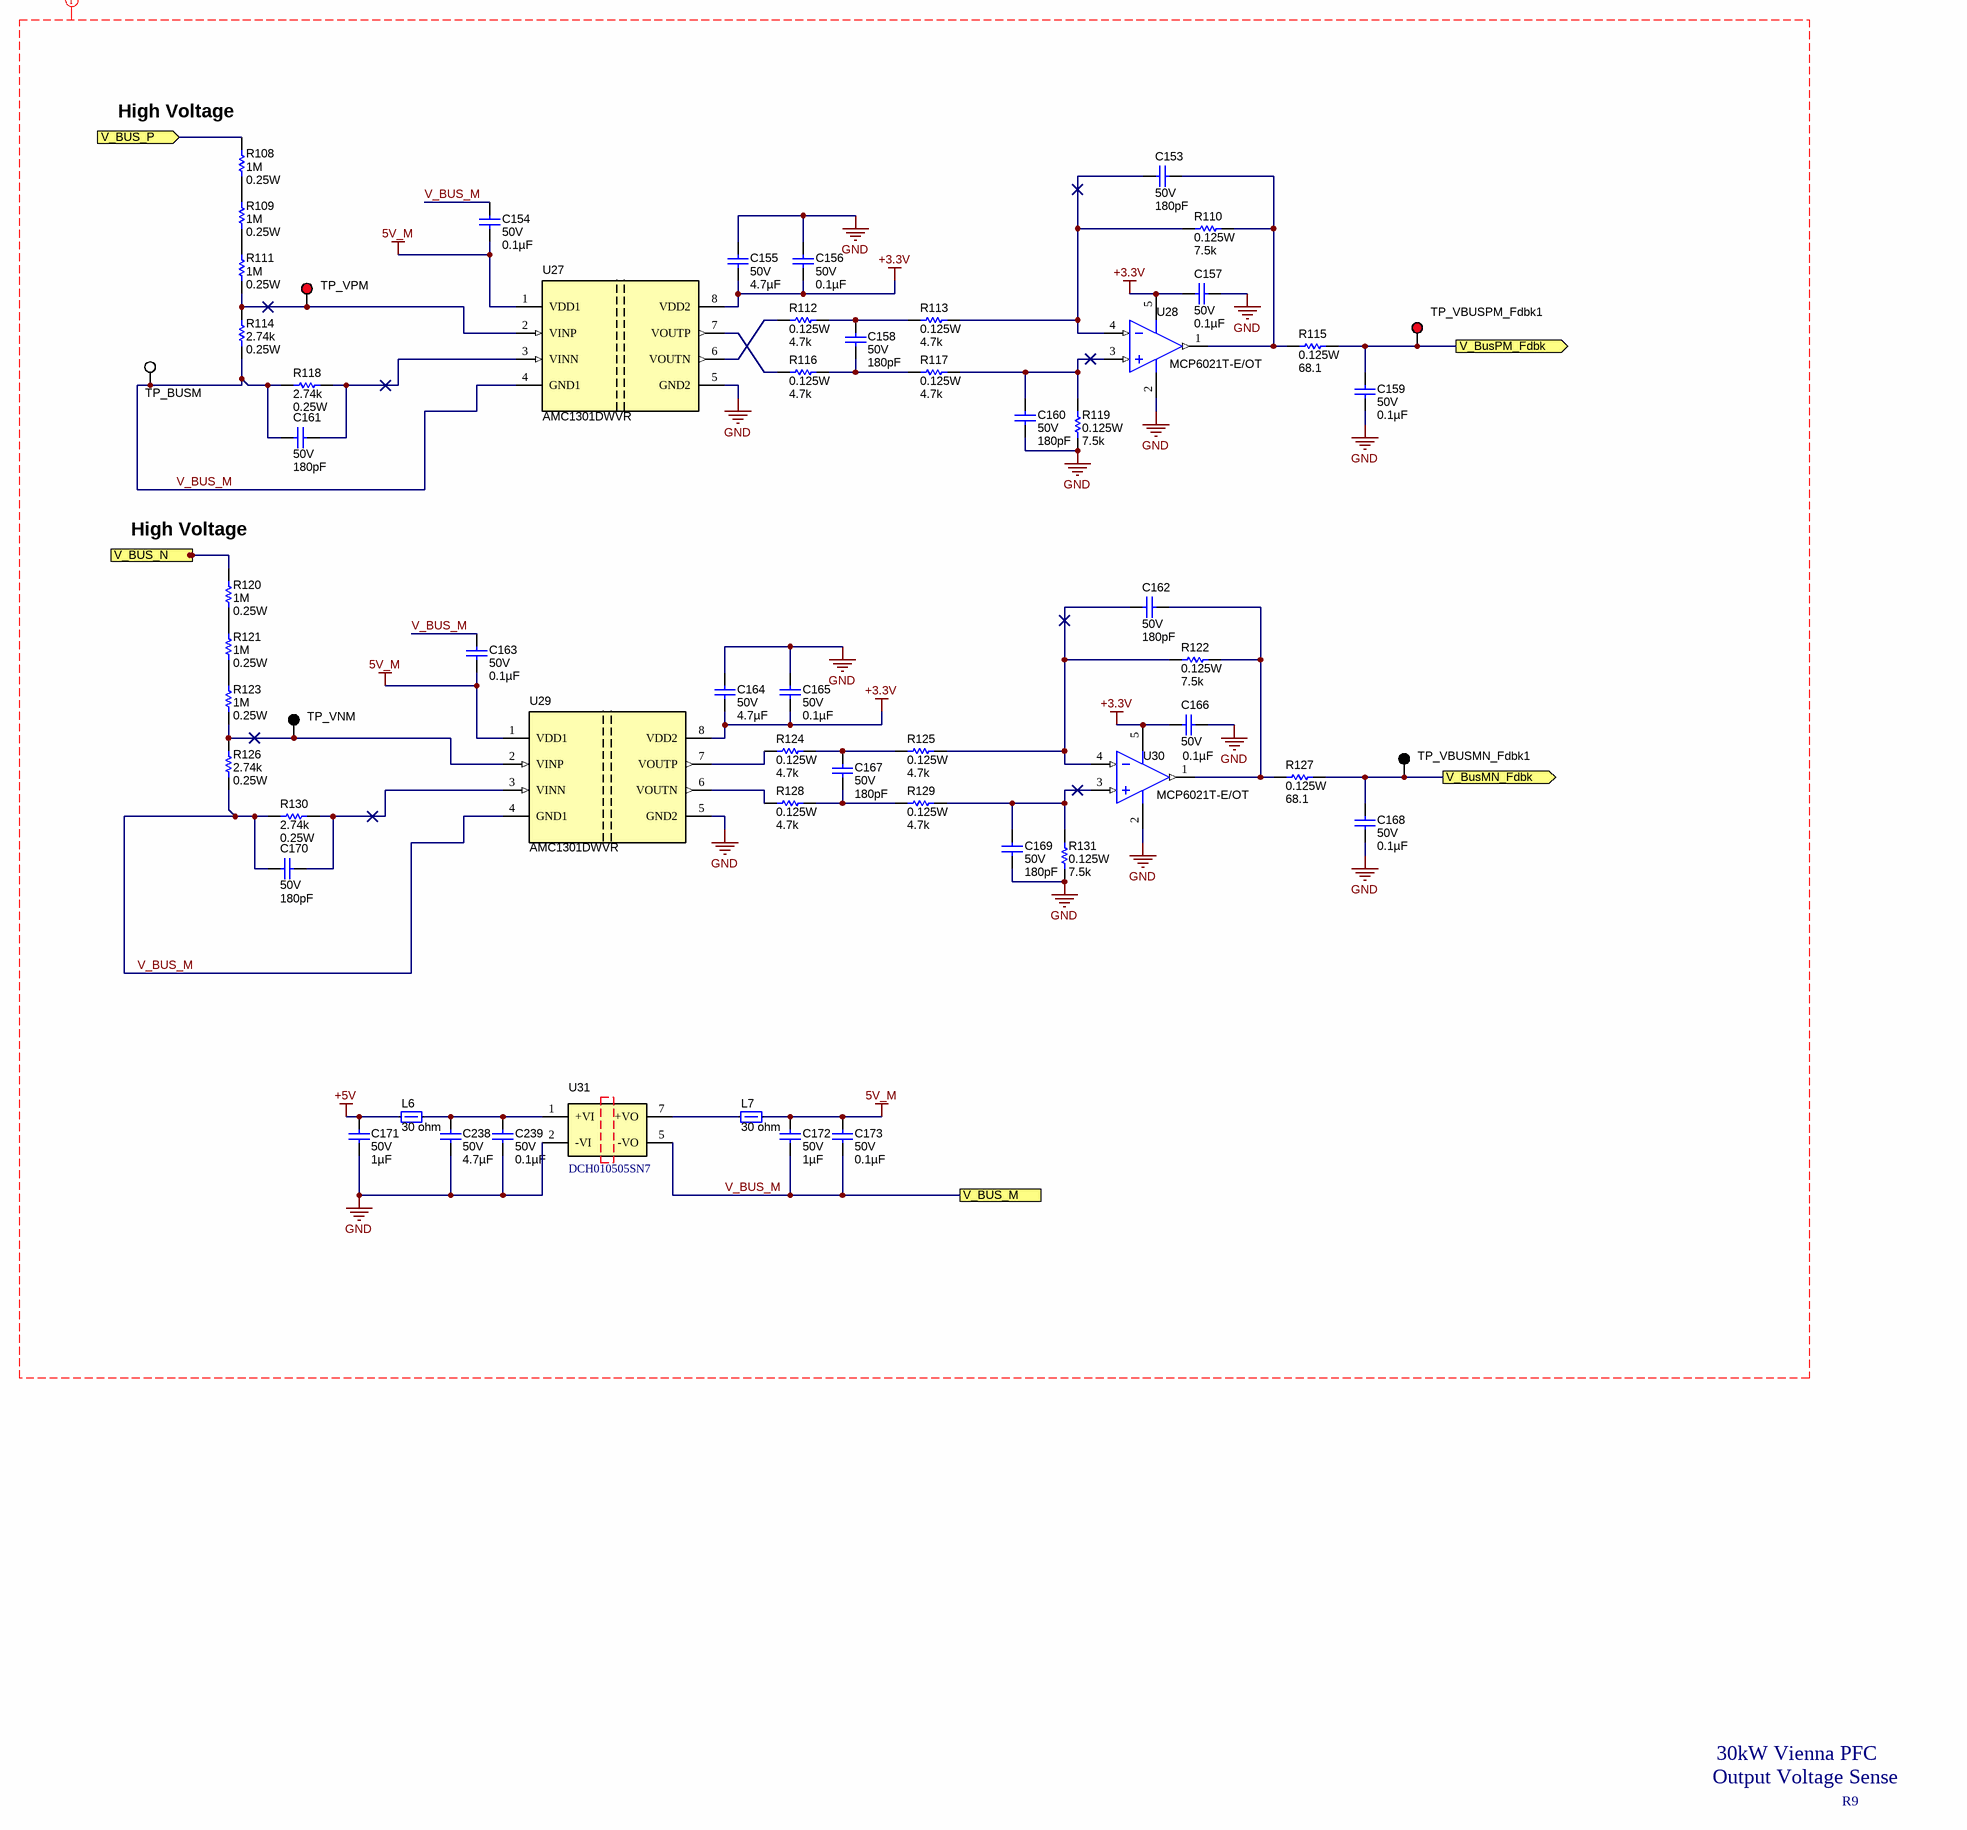
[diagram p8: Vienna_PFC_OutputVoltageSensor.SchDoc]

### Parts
(Parts that share a designator on the sheet are numbered #1, #2 ... from top to bottom, then left to right.)
?#6  (no value)  (graphical)
C153  VDC_V: 50V  ValueDisplayed: 180pF  [0805_HV]  (hidden comment: C0805C181J5GACTU)
C154  VDC_V: 50V  ValueDisplayed: 0.1µF  [0805_HV]  (hidden comment: C0805C104J5RACTU)
C155  VDC_V: 50V  ValueDisplayed: 4.7µF  [0805_HV]  (hidden comment: C2012X5R1H475K125AB)
C156  VDC_V: 50V  ValueDisplayed: 0.1µF  [0805_HV]  (hidden comment: C0805C104J5RACTU)
C157  VDC_V: 50V  ValueDisplayed: 0.1µF  [0805_HV]  (hidden comment: C0805C104J5RACTU)
C158  VDC_V: 50V  ValueDisplayed: 180pF  [0805_HV]  (hidden comment: C0805C181J5GACTU)
C159  VDC_V: 50V  ValueDisplayed: 0.1µF  [0805_HV]  (hidden comment: C0805C104J5RACTU)
C160  VDC_V: 50V  ValueDisplayed: 180pF  [0805_HV]  (hidden comment: C0805C181J5GACTU)
C161  VDC_V: 50V  ValueDisplayed: 180pF  [0805_HV]  (hidden comment: C0805C181J5GACTU)
C162  VDC_V: 50V  ValueDisplayed: 180pF  [0805_HV]  (hidden comment: C0805C181J5GACTU)
C163  VDC_V: 50V  ValueDisplayed: 0.1µF  [0805_HV]  (hidden comment: C0805C104J5RACTU)
C164  VDC_V: 50V  ValueDisplayed: 4.7µF  [0805_HV]  (hidden comment: C2012X5R1H475K125AB)
C165  VDC_V: 50V  ValueDisplayed: 0.1µF  [0805_HV]  (hidden comment: C0805C104J5RACTU)
C166  VDC_V: 50V  ValueDisplayed: 0.1µF  [0805_HV]  (hidden comment: C0805C104J5RACTU)
C167  VDC_V: 50V  ValueDisplayed: 180pF  [0805_HV]  (hidden comment: C0805C181J5GACTU)
C168  VDC_V: 50V  ValueDisplayed: 0.1µF  [0805_HV]  (hidden comment: C0805C104J5RACTU)
C169  VDC_V: 50V  ValueDisplayed: 180pF  [0805_HV]  (hidden comment: C0805C181J5GACTU)
C170  VDC_V: 50V  ValueDisplayed: 180pF  [0805_HV]  (hidden comment: C0805C181J5GACTU)
C171  VDC_V: 50V  ValueDisplayed: 1µF  [0805_HV]  (hidden comment: C0805C105K5RACTU)
C172  VDC_V: 50V  ValueDisplayed: 1µF  [0805_HV]  (hidden comment: C0805C105K5RACTU)
C173  VDC_V: 50V  ValueDisplayed: 0.1µF  [0805_HV]  (hidden comment: C0805C104J5RACTU)
C238  VDC_V: 50V  ValueDisplayed: 4.7µF  [0805_HV]  (hidden comment: C2012X5R1H475K125AB)
C239  VDC_V: 50V  ValueDisplayed: 0.1µF  [0805_HV]  (hidden comment: C0805C104J5RACTU)
L6  value 30 ohm  [0805_HV]  (hidden comment: MPZ2012S300AT000)
L7  value 30 ohm  [0805_HV]  (hidden comment: MPZ2012S300AT000)
R108  value 1M  Power_W: 0.25W  [1206_190]  (hidden comment: TNPW12061M00BXTY)
R109  value 1M  Power_W: 0.25W  [1206_190]  (hidden comment: TNPW12061M00BXTY)
R110  Value2: 0.125W  ValueDisplayed: 7.5k  [0805_HV]  (hidden comment: CRCW08057K50FKEA)
R111  value 1M  Power_W: 0.25W  [1206_190]  (hidden comment: TNPW12061M00BXTY)
R112  Value2: 0.125W  ValueDisplayed: 4.7k  [0805_HV]  (hidden comment: CRCW08054K70FKEA)
R113  Value2: 0.125W  ValueDisplayed: 4.7k  [0805_HV]  (hidden comment: CRCW08054K70FKEA)
R114  value 2.74k  Power_W: 0.25W  [1206_190]  (hidden comment: TNPW12062K74BEEN)
R115  Value2: 0.125W  ValueDisplayed: 68.1  [0805_HV]  (hidden comment: CRCW080568R1FKEA)
R116  Value2: 0.125W  ValueDisplayed: 4.7k  [0805_HV]  (hidden comment: CRCW08054K70FKEA)
R117  Value2: 0.125W  ValueDisplayed: 4.7k  [0805_HV]  (hidden comment: CRCW08054K70FKEA)
R118  value 2.74k  Power_W: 0.25W  [1206_190]  (hidden comment: TNPW12062K74BEEN)
R119  Value2: 0.125W  ValueDisplayed: 7.5k  [0805_HV]  (hidden comment: CRCW08057K50FKEA)
R120  value 1M  Power_W: 0.25W  [1206_190]  (hidden comment: TNPW12061M00BXTY)
R121  value 1M  Power_W: 0.25W  [1206_190]  (hidden comment: TNPW12061M00BXTY)
R122  Value2: 0.125W  ValueDisplayed: 7.5k  [0805_HV]  (hidden comment: CRCW08057K50FKEA)
R123  value 1M  Power_W: 0.25W  [1206_190]  (hidden comment: TNPW12061M00BXTY)
R124  Value2: 0.125W  ValueDisplayed: 4.7k  [0805_HV]  (hidden comment: CRCW08054K70FKEA)
R125  Value2: 0.125W  ValueDisplayed: 4.7k  [0805_HV]  (hidden comment: CRCW08054K70FKEA)
R126  value 2.74k  Power_W: 0.25W  [1206_190]  (hidden comment: TNPW12062K74BEEN)
R127  Value2: 0.125W  ValueDisplayed: 68.1  [0805_HV]  (hidden comment: CRCW080568R1FKEA)
R128  Value2: 0.125W  ValueDisplayed: 4.7k  [0805_HV]  (hidden comment: CRCW08054K70FKEA)
R129  Value2: 0.125W  ValueDisplayed: 4.7k  [0805_HV]  (hidden comment: CRCW08054K70FKEA)
R130  value 2.74k  Power_W: 0.25W  [1206_190]  (hidden comment: TNPW12062K74BEEN)
R131  Value2: 0.125W  ValueDisplayed: 7.5k  [0805_HV]  (hidden comment: CRCW08057K50FKEA)
TP_BUSM  5012  [Keystone5012]  (value not drawn)
TP_VBUSMN_Fdbk1  5011  [Keystone5011]  (value not drawn)
TP_VBUSPM_Fdbk1  5010  [Keystone5010]  (value not drawn)
TP_VNM  5011  [Keystone5011]  (value not drawn)
TP_VPM  5010  [Keystone5010]  (value not drawn)
U27  AMC1301DWVR  [AMC1301]
U28  MCP6021T-E/OT  [OPA320]
U29  AMC1301DWVR  [AMC1301]
U30  MCP6021T-E/OT  [OPA320]
U31  DCH010505SN7  [DCH010505SN7]

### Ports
V_BUS_M, V_BUS_N (in), V_BUS_P (in), V_BusMN_Fdbk (out), V_BusPM_Fdbk (out)

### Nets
5V_M: C154.2 C163.2 C172.1 C173.1 L7.2 U27.1(VDD1) U29.1(VDD1)
+3.3V: C155.2 C156.2 C157.1 C164.2 C165.2 C166.1 U27.8(VDD2) U28.5(V+) U29.8(VDD2) U30.5(V+)
+5V: C171.1 L6.1
GND: C155.1 C156.1 C157.2 C159.1 C160.2 C164.1 C165.1 C166.2 C168.1 C169.2 C171.2 C238.2 C239.2 R119.1 R131.1 U27.5(GND2) U28.2(V-) U29.5(GND2) U30.2(V-) U31.2(-VI)
V_BUS_M: C154.1 C161.2 C163.1 C170.2 C172.2 C173.2 R114.1 R118.2 R126.1 R130.2 TP_BUSM.1 U27.4(GND1) U29.4(GND1) U31.5(-VO) ; port V_BUS_M
VBUSN: R120.2 ; port V_BUS_N
VBUSP: R108.2 ; port V_BUS_P
NetC153_1: C153.1 R110.2 R115.1 U28.1(OUT)
NetC153_2: C153.2 R110.1 R113.2 U28.4(IN-)
NetC158_1: C158.1 R112.2 R113.1
NetC158_2: C158.2 R116.2 R117.1
NetC159_2: C159.2 R115.2 TP_VBUSPM_Fdbk1.1 ; port V_BusPM_Fdbk
NetC160_1: C160.1 R117.2 R119.2 U28.3(IN+)
NetC161_1: C161.1 R118.1 U27.3(VINN)
NetC162_1: C162.1 R122.2 R127.1 U30.1(OUT)
NetC162_2: C162.2 R122.1 R125.2 U30.4(IN-)
NetC167_1: C167.1 R124.2 R125.1
NetC167_2: C167.2 R128.2 R129.1
NetC168_2: C168.2 R127.2 TP_VBUSMN_Fdbk1.1 ; port V_BusMN_Fdbk
NetC169_1: C169.1 R129.2 R131.2 U30.3(IN+)
NetC170_1: C170.1 R130.1 U29.3(VINN)
NetC238_1: C238.1 C239.1 L6.2 U31.1(+VI)
NetL7_1: L7.1 U31.7(+VO)
NetR108_1: R108.1 R109.2
NetR109_1: R109.1 R111.2
NetR111_1: R111.1 R114.2 TP_VPM.1 U27.2(VINP)
NetR112_1: R112.1 U27.6(VOUTN)
NetR116_1: R116.1 U27.7(VOUTP)
NetR120_1: R120.1 R121.2
NetR121_1: R121.1 R123.2
NetR123_1: R123.1 R126.2 TP_VNM.1 U29.2(VINP)
NetR124_1: R124.1 U29.7(VOUTP)
NetR128_1: R128.1 U29.6(VOUTN)

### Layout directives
net class OutputVoltage: 5V_M, +3.3V, +5V, GND, V_BUS_M

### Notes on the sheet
- (near R108) High Voltage
- (near R120) High Voltage
- 30kW Vienna PFC
- Output Voltage Sense
- R9

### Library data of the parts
?#6 = Title Block C
C153 C158 C160-C162 C167 C169 C170 = C0805C181J5GACTU: CAP, CERM, 180 pF, 50 V, +/- 5%, X7R, 0805; Manufacturer: Kemet; CompType: Capacitor; Tolerance_%: 5; TaMin_C: -55; TaMax_C: 125; Cap_Case: 0805; AEC Category: Q200
C154 C156 C157 C159 C163 C165 C166 C168 C173 C239 = C0805C104J5RACTU: as C21 on sheet Vienna_PFC_GateDriver
C155 C164 C238 = C2012X5R1H475K125AB: as C28 on sheet Vienna_PFC_GateDriver
C171 C172 = C0805C105K5RACTU: as C22 on sheet Vienna_PFC_GateDriver
L6 L7 = MPZ2012S300AT000: as L1 on sheet Vienna_PFC_GateDriver
R108 R109 R111 R120 R121 R123 = TNPW12061M00BXTY: RES, 1 M, 0.1%, 0.25 W, 15 PPM / C, AEC-Q200; Manufacturer: Vishay; CompType: Resistor; Tolerance_%: 0.1; VDC_V: 200V; AEC Category: Q200
R110 R119 R122 R131 = CRCW08057K50FKEA: RES, 7.5K, 1%, 0.125 W, 0805; Manufacturer: Vishay-Dale; CompType: Resistor; Value: 348; Tolerance_%: 1; Power_W: 0.125; VDC_V: 150; TempCo: 100 ppm/C; EIA_Code: E96; U/M: EA; AEC Category: Q200
R112 R113 R116 R117 R124 R125 R128 R129 = CRCW08054K70FKEA: RES, 4.7K, 1%, 0.125 W, 0805; Manufacturer: Vishay-Dale; CompType: Resistor; Tolerance_%: 1; Power_W: 0.125; VDC_V: 150; TempCo: 100 ppm/C; EIA_Code: E96; U/M: EA; AEC Category: Q200
R114 R118 R126 R130 = TNPW12062K74BEEN: RES, 2.74 k,  0.1%, 0.25 W, 25 PPM / C, AEC-Q200; Manufacturer: Vishay; CompType: Resistor; Tolerance_%: 0.1; VDC_V: 200V; AEC Category: Q200
R115 R127 = CRCW080568R1FKEA: RES, 68.1, 1%, 0.125 W, 0805; Manufacturer: Vishay-Dale; CompType: Resistor; Value: 348; Value_Code: 68R1; Tolerance_%: 1; Power_W: 0.125; VDC_V: 150; TempCo: 100 ppm/C; EIA_Code: E96; U/M: EA; AEC Category: Q200
TP_BUSM = 5012: as TP_G2 on sheet Vienna_PFC_GateDriver
TP_VBUSMN_Fdbk1 TP_VNM = 5011: as TP_DGND1 on sheet Vienna_PFC_GateDriver
TP_VBUSPM_Fdbk1 TP_VPM = 5010: as TP_G1 on sheet Vienna_PFC_GateDriver
U27 U29 = AMC1301DWVR: Precision +/-250-mV Input, 3-us Delay, Reinforced Isolated Amplifier, DWV0008A (SOIC-8); Manufacturer: Texas Instruments; SymbolCreator: Altium; SizeArea_mm2: 67.275; SizeAreaWB_mm2: 105.975; SizeX_mm: 11.5; SizeY_mm: 5.85; SizeZ_mm: 2.8; CompType: IC; U/M: EA
U28 U30 = MCP6021T-E/OT: General Purpose Amplifier 1 Circuit Rail-to-Rail SOT-23-5; Manufacturer: Microchip Technology; Number of Channels: 2; Offset Drift(Typ)(uV/C): 1.5; Total Supply Voltage(Max)(+5V is 5, +/-5V is 10): 5.5; Total Supply Voltage(Min)(+5V is 5, +/-5V is 10): 2.5
U31 = DCH010505SN7: Miniature, 1 W, 3 kVDC Isolated DC-DC Converter, -40 to 85 degC, 4-pin Module (EDJ4), Pb-Free (RoHS); Manufacturer: Texas Instruments; Alternate PartNumber: Equivalent; Iout(Max)(A): 0.2; Regulated Outputs(#): 1; SubFamily: 1 W & 2 W Miniature; Vin(Max)(V): 5.5; Vin(Min)(V): 4.5

## Sheet Vienna_PFC_InductorCurrentSensor.SchDoc
size C; DocumentNumber: 5; SheetNumber: 5; SheetTotal: 11
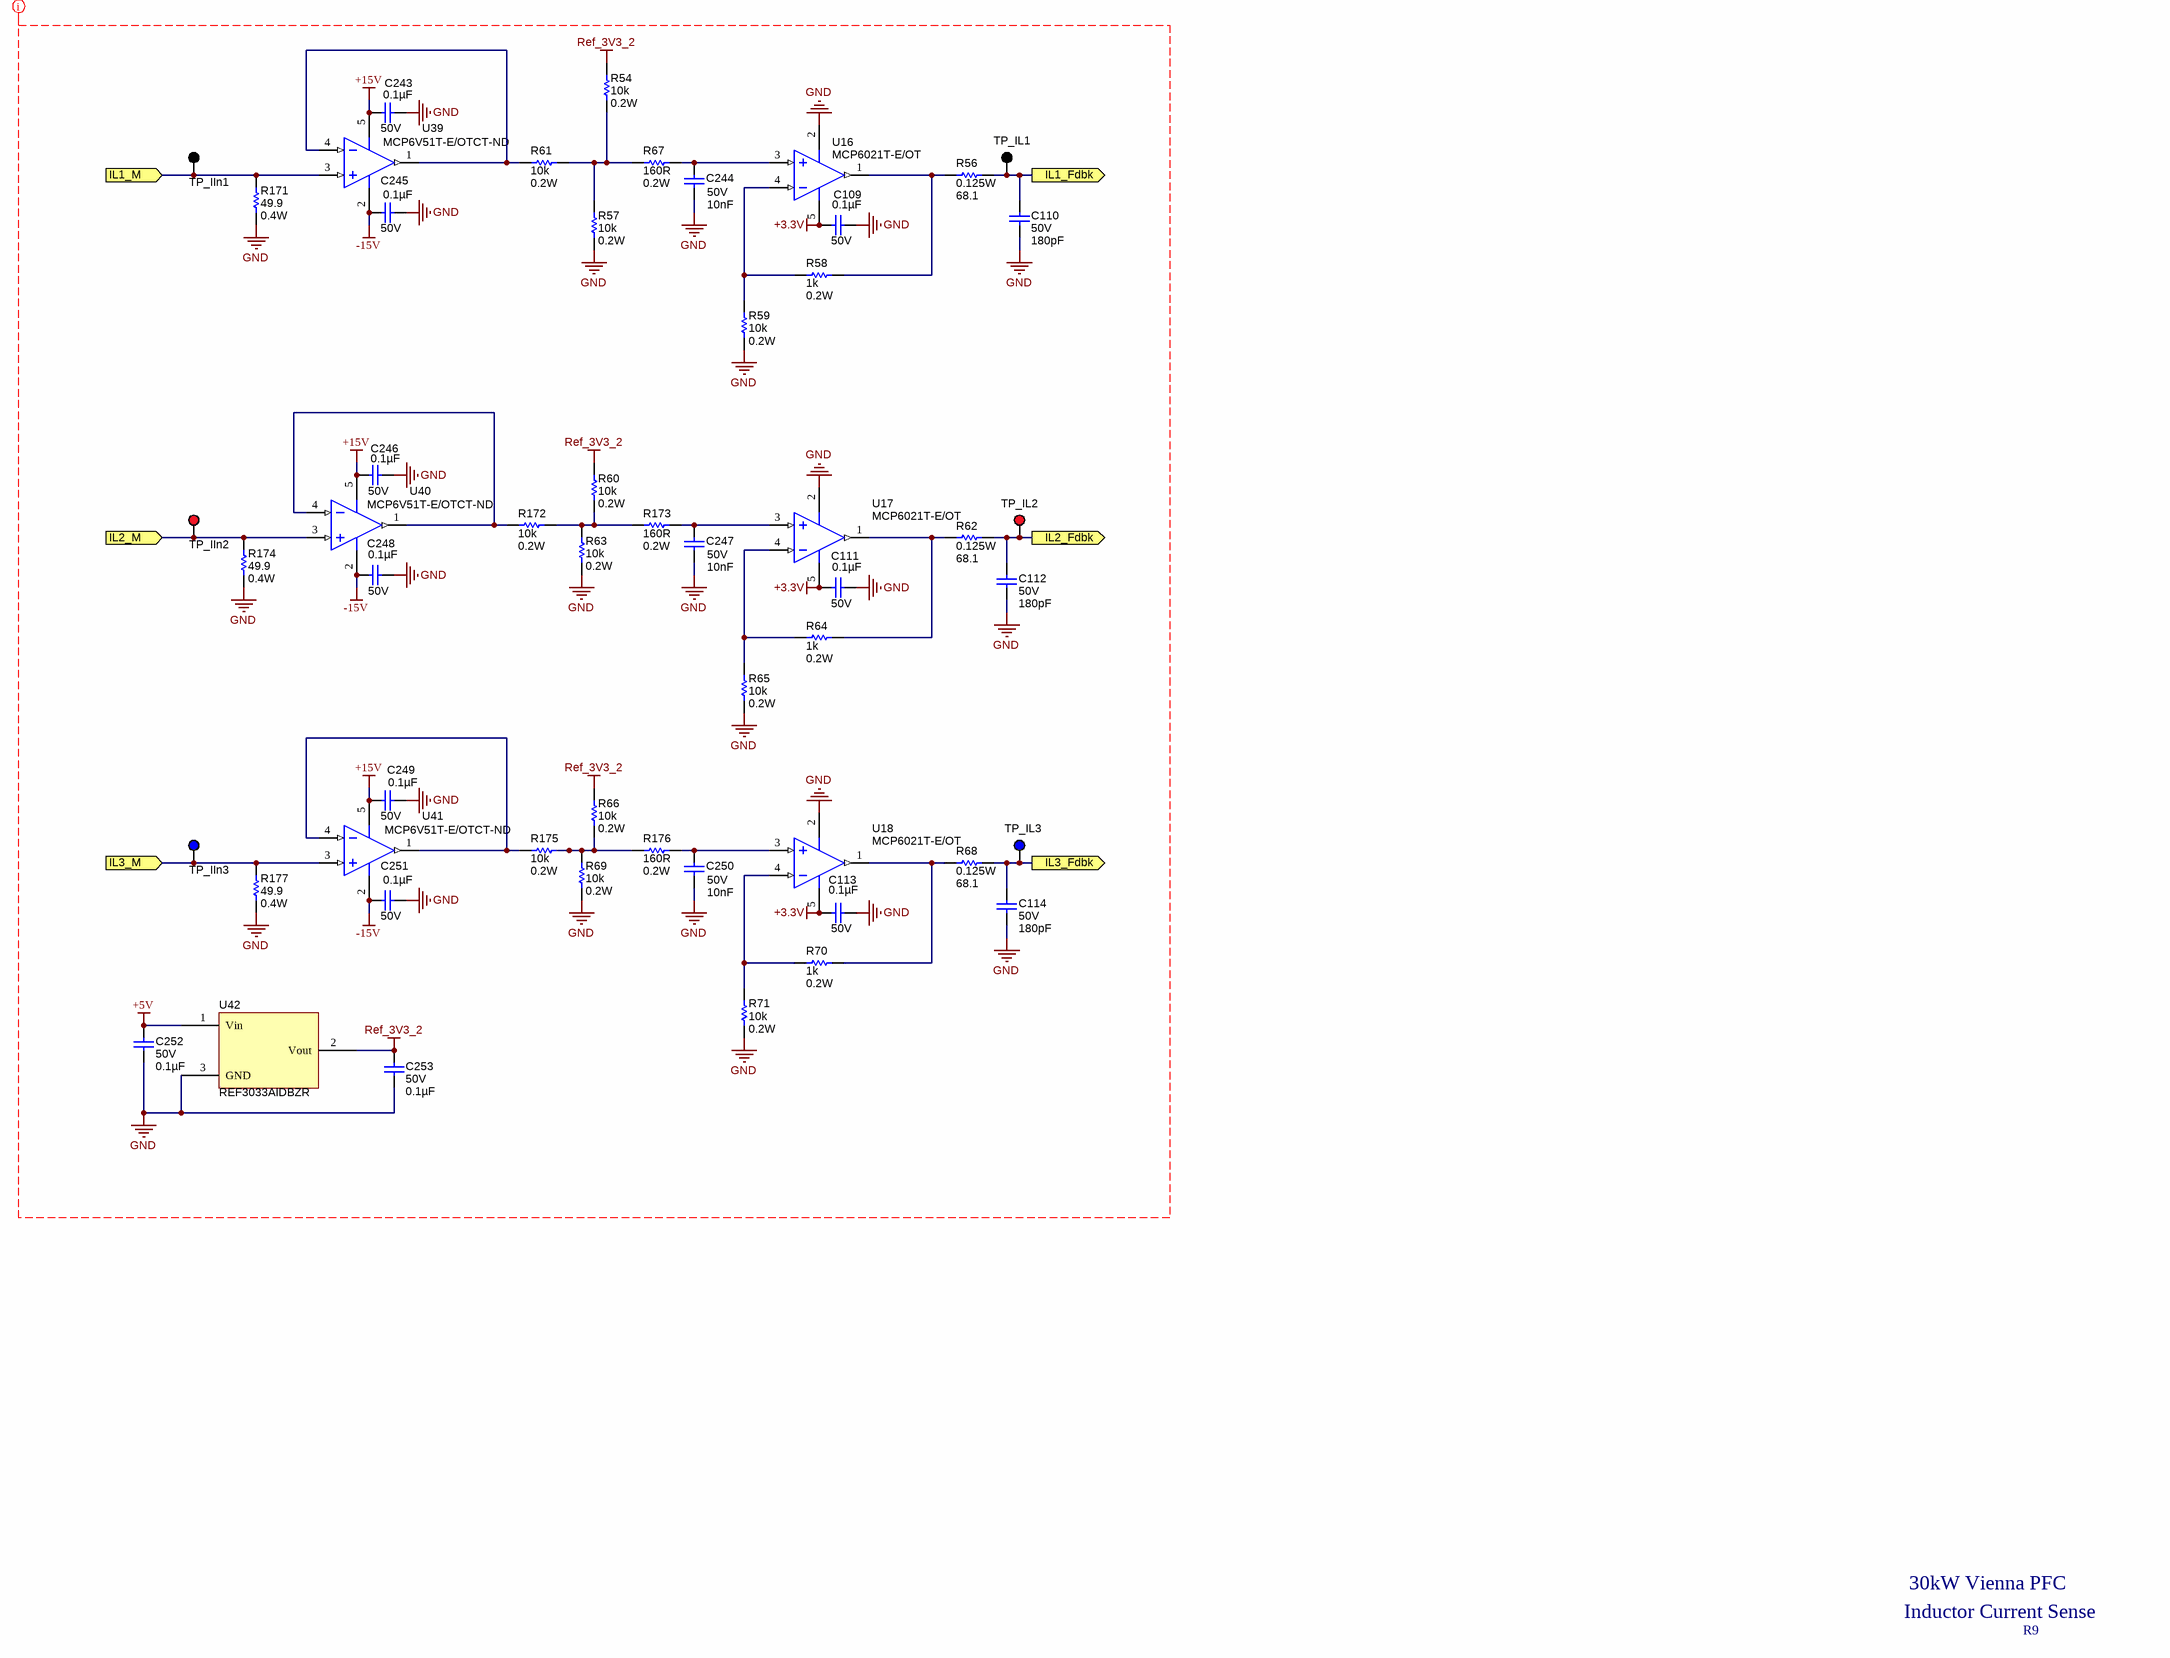
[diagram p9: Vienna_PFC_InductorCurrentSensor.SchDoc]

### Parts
(Parts that share a designator on the sheet are numbered #1, #2 ... from top to bottom, then left to right.)
?#7  (no value)  (graphical)
C109  VDC_V: 50V  ValueDisplayed: 0.1µF  [0805_HV]  (hidden comment: C0805C104J5RACTU)
C110  VDC_V: 50V  ValueDisplayed: 180pF  [0805_HV]  (hidden comment: C0805C181J5GACTU)
C111  VDC_V: 50V  ValueDisplayed: 0.1µF  [0805_HV]  (hidden comment: C0805C104J5RACTU)
C112  VDC_V: 50V  ValueDisplayed: 180pF  [0805_HV]  (hidden comment: C0805C181J5GACTU)
C113  VDC_V: 50V  ValueDisplayed: 0.1µF  [0805_HV]  (hidden comment: C0805C104J5RACTU)
C114  VDC_V: 50V  ValueDisplayed: 180pF  [0805_HV]  (hidden comment: C0805C181J5GACTU)
C243  VDC_V: 50V  ValueDisplayed: 0.1µF  [0805_HV]  (hidden comment: C0805C104J5RACTU)
C244  VDC_V: 50V  ValueDisplayed: 10nF  [0805_HV]  (hidden comment: C0805C103J5RACTU)
C245  VDC_V: 50V  ValueDisplayed: 0.1µF  [0805_HV]  (hidden comment: C0805C104J5RACTU)
C246  VDC_V: 50V  ValueDisplayed: 0.1µF  [0805_HV]  (hidden comment: C0805C104J5RACTU)
C247  VDC_V: 50V  ValueDisplayed: 10nF  [0805_HV]  (hidden comment: C0805C103J5RACTU)
C248  VDC_V: 50V  ValueDisplayed: 0.1µF  [0805_HV]  (hidden comment: C0805C104J5RACTU)
C249  VDC_V: 50V  ValueDisplayed: 0.1µF  [0805_HV]  (hidden comment: C0805C104J5RACTU)
C250  VDC_V: 50V  ValueDisplayed: 10nF  [0805_HV]  (hidden comment: C0805C103J5RACTU)
C251  VDC_V: 50V  ValueDisplayed: 0.1µF  [0805_HV]  (hidden comment: C0805C104J5RACTU)
C252  VDC_V: 50V  ValueDisplayed: 0.1µF  [0805_HV]  (hidden comment: C0805C104J5RACTU)
C253  VDC_V: 50V  ValueDisplayed: 0.1µF  [0805_HV]  (hidden comment: C0805C104J5RACTU)
R54  value 10k  Power_W: 0.2W  [0805_HV]  (hidden comment: TNPW08052K20BEEA)
R56  Value2: 0.125W  ValueDisplayed: 68.1  [0805_HV]  (hidden comment: CRCW080568R1FKEA)
R57  value 10k  Power_W: 0.2W  [0805_HV]  (hidden comment: TNPW080540K2BEEA)
R58  value 1k  Power_W: 0.2W  [0805_HV]
R59  value 10k  Power_W: 0.2W  [0805_HV]  (hidden comment: TNPW080510K0BEEA)
R60  value 10k  Power_W: 0.2W  [0805_HV]  (hidden comment: TNPW08052K20BEEA)
R61  value 10k  Power_W: 0.2W  [0805_HV]  (hidden comment: TNPW08052K20BEEA)
R62  Value2: 0.125W  ValueDisplayed: 68.1  [0805_HV]  (hidden comment: CRCW080568R1FKEA)
R63  value 10k  Power_W: 0.2W  [0805_HV]  (hidden comment: TNPW080540K2BEEA)
R64  value 1k  Power_W: 0.2W  [0805_HV]
R65  value 10k  Power_W: 0.2W  [0805_HV]  (hidden comment: TNPW080510K0BEEA)
R66  value 10k  Power_W: 0.2W  [0805_HV]  (hidden comment: TNPW08052K20BEEA)
R67  value 160R  Power_W: 0.2W  [0805_HV]  (hidden comment: TNPW0805160RBEEA)
R68  Value2: 0.125W  ValueDisplayed: 68.1  [0805_HV]  (hidden comment: CRCW080568R1FKEA)
R69  value 10k  Power_W: 0.2W  [0805_HV]  (hidden comment: TNPW080540K2BEEA)
R70  value 1k  Power_W: 0.2W  [0805_HV]
R71  value 10k  Power_W: 0.2W  [0805_HV]  (hidden comment: TNPW080510K0BEEA)
R171  value 49.9  Power_W: 0.4W  [1206_190]  (hidden comment: TNPW120649R9BEEA)
R172  value 10k  Power_W: 0.2W  [0805_HV]  (hidden comment: TNPW08052K20BEEA)
R173  value 160R  Power_W: 0.2W  [0805_HV]  (hidden comment: TNPW0805160RBEEA)
R174  value 49.9  Power_W: 0.4W  [1206_190]  (hidden comment: TNPW120649R9BEEA)
R175  value 10k  Power_W: 0.2W  [0805_HV]  (hidden comment: TNPW08052K20BEEA)
R176  value 160R  Power_W: 0.2W  [0805_HV]  (hidden comment: TNPW0805160RBEEA)
R177  value 49.9  Power_W: 0.4W  [1206_190]  (hidden comment: TNPW120649R9BEEA)
TP_IIn1  5011  [Keystone5011]  (value not drawn)
TP_IIn2  5010  [Keystone5010]  (value not drawn)
TP_IIn3  5127  [Keystone5127]  (value not drawn)
TP_IL1  5011  [Keystone5011]  (value not drawn)
TP_IL2  5010  [Keystone5010]  (value not drawn)
TP_IL3  5127  [Keystone5127]  (value not drawn)
U16  MCP6021T-E/OT  [OPA320]
U17  MCP6021T-E/OT  [OPA320]
U18  MCP6021T-E/OT  [OPA320]
U39  MCP6V51T-E/OTCT-ND  [OPA192]
U40  MCP6V51T-E/OTCT-ND  [OPA192]
U41  MCP6V51T-E/OTCT-ND  [OPA192]
U42  REF3033AIDBZR  [SOT-23]

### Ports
IL1_Fdbk (out), IL1_M (in), IL2_Fdbk (out), IL2_M (in), IL3_Fdbk (out), IL3_M (in)

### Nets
+3.3V: C109.1 C111.1 C113.1 U16.5(V+) U17.5(V+) U18.5(V+)
+5V: C252.1 U42.1(Vin)
+15V: C243.1 C246.1 C249.1 U39.5(V+) U40.5(V+) U41.5(V+)
-15V: C245.1 C248.1 C251.1 U39.2(V-) U40.2(V-) U41.2(V-)
GND: C109.2 C110.2 C111.2 C112.2 C113.2 C114.2 C243.2 C244.2 C245.2 C246.2 C247.2 C248.2 C249.2 C250.2 C251.2 C252.2 C253.2 R57.1 R59.1 R63.1 R65.1 R69.1 R71.1 R171.1 R174.1 R177.1 U16.2(V-) U17.2(V-) U18.2(V-) U42.3(GND)
Ref_3V3_2: C253.1 R54.2 R60.2 R66.2 U42.2(Vout)
NetC110_1: C110.1 R56.2 TP_IL1.1 ; port IL1_Fdbk
NetC112_1: C112.1 R62.2 TP_IL2.1 ; port IL2_Fdbk
NetC114_1: C114.1 R68.2 TP_IL3.1 ; port IL3_Fdbk
NetC244_1: C244.1 R67.2 U16.3(IN+)
NetC247_1: C247.1 R173.2 U17.3(IN+)
NetC250_1: C250.1 R176.2 U18.3(IN+)
NetR54_1: R54.1 R57.2 R61.2 R67.1
NetR56_1: R56.1 R58.2 U16.1(OUT)
NetR58_1: R58.1 R59.2 U16.4(IN-)
NetR60_1: R60.1 R63.2 R172.2 R173.1
NetR61_1: R61.1 U39.1(OUT) U39.4(IN-)
NetR62_1: R62.1 R64.2 U17.1(OUT)
NetR64_1: R64.1 R65.2 U17.4(IN-)
NetR66_1: R66.1 R69.2 R175.2 R176.1
NetR68_1: R68.1 R70.2 U18.1(OUT)
NetR70_1: R70.1 R71.2 U18.4(IN-)
NetR171_2: R171.2 TP_IIn1.1 U39.3(IN+) ; port IL1_M
NetR172_1: R172.1 U40.1(OUT) U40.4(IN-)
NetR174_2: R174.2 TP_IIn2.1 U40.3(IN+) ; port IL2_M
NetR175_1: R175.1 U41.1(OUT) U41.4(IN-)
NetR177_2: R177.2 TP_IIn3.1 U41.3(IN+) ; port IL3_M

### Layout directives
net class InductorCurrent: +3.3V, +5V, +15V, -15V, GND, Ref_3V3_2

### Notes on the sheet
- 30kW Vienna PFC
- Inductor Current Sense
- R9

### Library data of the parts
?#7 = Title Block C
C109 C111 C113 C243 C245 C246 C248 C249 C251-C253 = C0805C104J5RACTU: as C21 on sheet Vienna_PFC_GateDriver
C110 C112 C114 = C0805C181J5GACTU: as C153 on sheet Vienna_PFC_OutputVoltageSensor
C244 C247 C250 = C0805C103J5RACTU: CAP, CERM, 10 nF, 50 V, +/- 5%, X7R, 0805; Manufacturer: Kemet; CompType: Capacitor; Tolerance_%: 5; TaMin_C: -55; TaMax_C: 125; Cap_Case: 0805; AEC Category: Q200
R54 R60 R61 R66 R172 R175 = TNPW08052K20BEEA: as R14 on sheet Vienna_PFC_GateDriver
R56 R62 R68 = CRCW080568R1FKEA: as R115 on sheet Vienna_PFC_OutputVoltageSensor
R57 R63 R69 = TNPW080540K2BEEA: RES 40.2K OHM 0.1% 1/5W 0805; Manufacturer: Vishay; CompType: Resistor; Tolerance_%: 0.1; VDC_V: 200V; TempCo: 25ppm/C; AEC Category: Q200
R58 R64 R70 = TNPW08051K00BEEA: RES 1K OHM 0.1% 1/5W 0805; Manufacturer: Vishay; CompType: Resistor; Tolerance_%: 0.1; VDC_V: 200V; TempCo: 25ppm/C; AEC Category: Q200
R59 R65 R71 = TNPW080510K0BEEA: RES 10K OHM 0.1% 1/5W 0805; Manufacturer: Vishay; CompType: Resistor; Tolerance_%: 0.1; VDC_V: 200V; TempCo: 25ppm/C; AEC Category: Q200
R67 R173 R176 = TNPW0805160RBEEA: RES 160R OHM 0.1% 1/5W 0805; Manufacturer: Vishay; CompType: Resistor; Tolerance_%: 0.1; VDC_V: 200V; TempCo: 25ppm/C; AEC Category: Q200
R171 R174 R177 = TNPW120649R9BEEA: RES, 49.9  0.1%, 0.4 W, 25 PPM / C, AEC-Q200; Manufacturer: Vishay; CompType: Resistor; Tolerance_%: 0.1; VDC_V: 200V; AEC Category: Q200
TP_IIn1 TP_IL1 = 5011: as TP_DGND1 on sheet Vienna_PFC_GateDriver
TP_IIn2 TP_IL2 = 5010: as TP_G1 on sheet Vienna_PFC_GateDriver
TP_IIn3 TP_IL3 = 5127: as TP_EN1 on sheet Vienna_PFC_GateDriver
U16-U18 = MCP6021T-E/OT: as U28 on sheet Vienna_PFC_OutputVoltageSensor
U39-U41 = MCP6V51T-E/OT: SINGLE, 45V ZERO-DRIFT OP AMP, E; Alternate Manufacturer: Microchip Technology
U42 = REF3033AIDBZR: IC VREF SERIES 3.3V SOT23-3; Manufacturer: Texas Instruments; Number of Channels: 2

## Sheet Vienna_PFC_PowerSupply.SchDoc
size C; DocumentNumber: 8; SheetNumber: 8; SheetTotal: 11
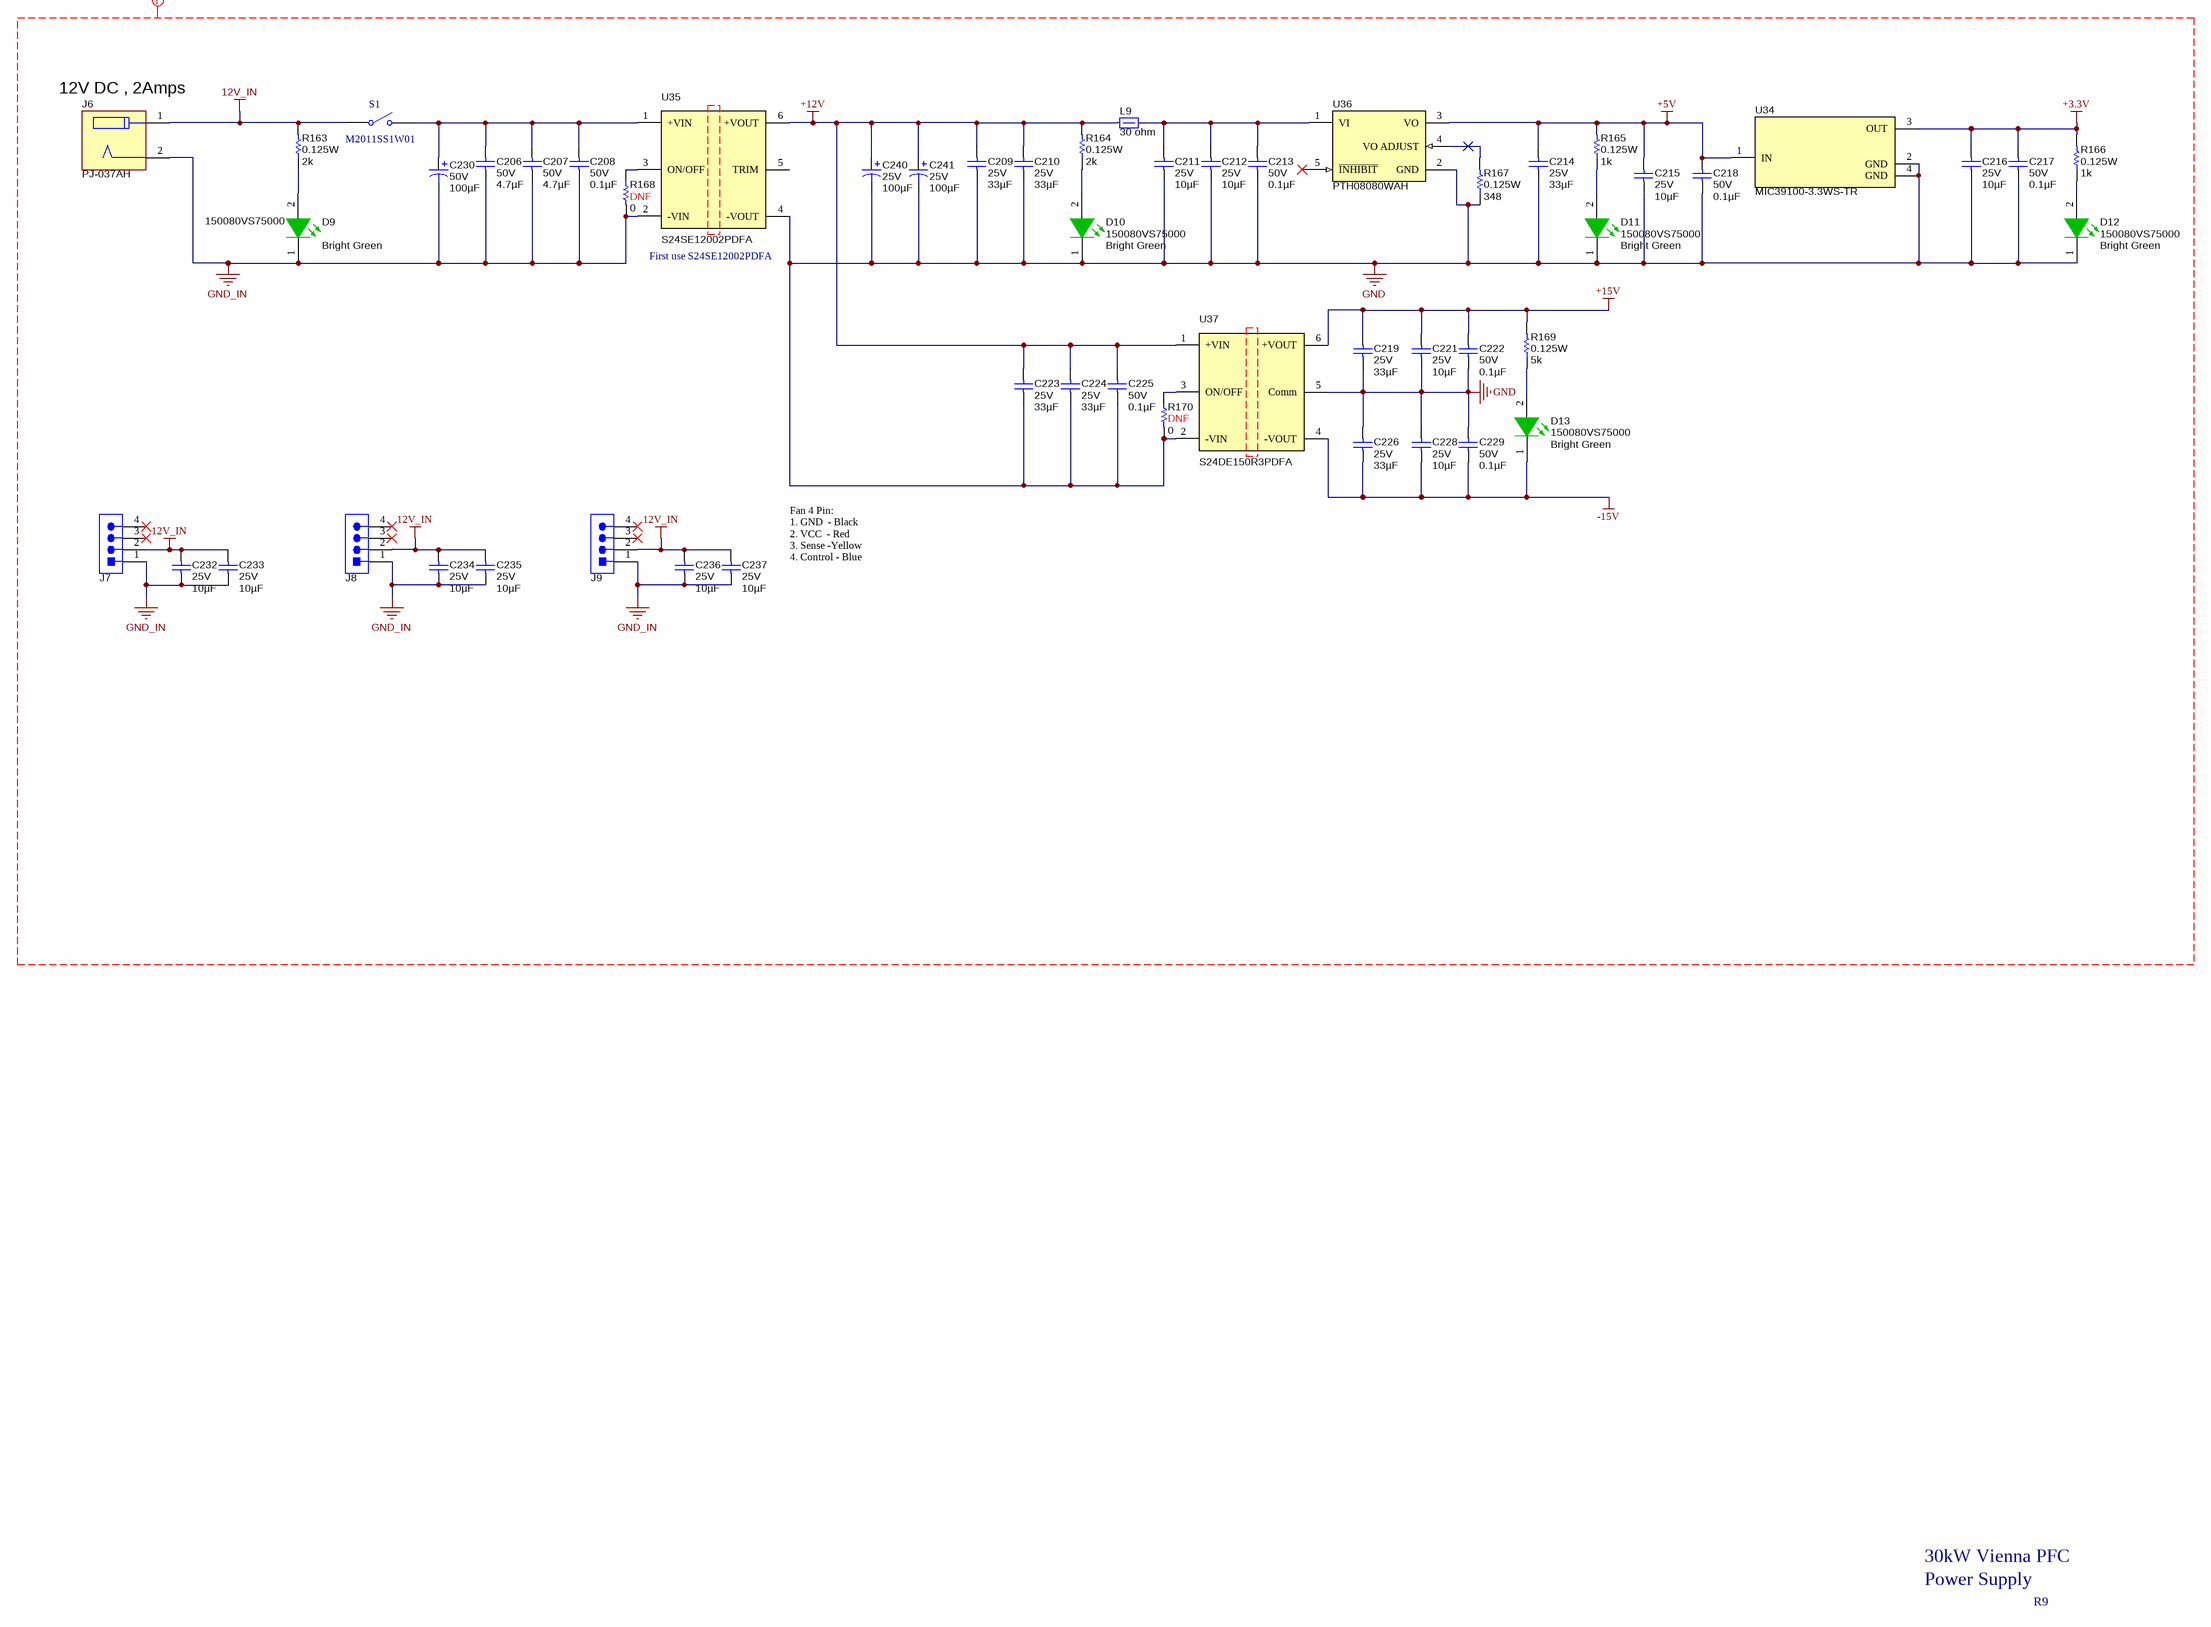
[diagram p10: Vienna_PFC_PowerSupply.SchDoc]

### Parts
(Parts that share a designator on the sheet are numbered #1, #2 ... from top to bottom, then left to right.)
?#8  (no value)  (graphical)
C206  VDC_V: 50V  ValueDisplayed: 4.7µF  [0805_HV]  (hidden comment: C2012X5R1H475K125AB)
C207  VDC_V: 50V  ValueDisplayed: 4.7µF  [0805_HV]  (hidden comment: C2012X5R1H475K125AB)
C208  VDC_V: 50V  ValueDisplayed: 0.1µF  [0805_HV]  (hidden comment: C0805C104J5RACTU)
C209  VDC_V: 25V  ValueDisplayed: 33µF  [1206_190]  (hidden comment: C3216X5R1E336M160AC)
C210  VDC_V: 25V  ValueDisplayed: 33µF  [1206_190]  (hidden comment: C3216X5R1E336M160AC)
C211  VDC_V: 25V  ValueDisplayed: 10µF  [1206_190]  (hidden comment: C1206C106K3RACAUTO)
C212  VDC_V: 25V  ValueDisplayed: 10µF  [1206_190]  (hidden comment: C1206C106K3RACAUTO)
C213  VDC_V: 50V  ValueDisplayed: 0.1µF  [0805_HV]  (hidden comment: C0805C104J5RACTU)
C214  VDC_V: 25V  ValueDisplayed: 33µF  [1206_190]  (hidden comment: C3216X5R1E336M160AC)
C215  VDC_V: 25V  ValueDisplayed: 10µF  [1206_190]  (hidden comment: C1206C106K3RACAUTO)
C216  VDC_V: 25V  ValueDisplayed: 10µF  [1206_190]  (hidden comment: C1206C106K3RACAUTO)
C217  VDC_V: 50V  ValueDisplayed: 0.1µF  [0805_HV]  (hidden comment: C0805C104J5RACTU)
C218  VDC_V: 50V  ValueDisplayed: 0.1µF  [0805_HV]  (hidden comment: C0805C104J5RACTU)
C219  VDC_V: 25V  ValueDisplayed: 33µF  [1206_190]  (hidden comment: C3216X5R1E336M160AC)
C221  VDC_V: 25V  ValueDisplayed: 10µF  [1206_190]  (hidden comment: C1206C106K3RACAUTO)
C222  VDC_V: 50V  ValueDisplayed: 0.1µF  [0805_HV]  (hidden comment: C0805C104J5RACTU)
C223  VDC_V: 25V  ValueDisplayed: 33µF  [1206_190]  (hidden comment: C3216X5R1E336M160AC)
C224  VDC_V: 25V  ValueDisplayed: 33µF  [1206_190]  (hidden comment: C3216X5R1E336M160AC)
C225  VDC_V: 50V  ValueDisplayed: 0.1µF  [0805_HV]  (hidden comment: C0805C104J5RACTU)
C226  VDC_V: 25V  ValueDisplayed: 33µF  [1206_190]  (hidden comment: C3216X5R1E336M160AC)
C228  VDC_V: 25V  ValueDisplayed: 10µF  [1206_190]  (hidden comment: C1206C106K3RACAUTO)
C229  VDC_V: 50V  ValueDisplayed: 0.1µF  [0805_HV]  (hidden comment: C0805C104J5RACTU)
C230  VDC_V: 50V  ValueDisplayed: 100µF  [SM_RADIAL_10BMM]  (hidden comment: EEH-ZA1H101V)
C232  VDC_V: 25V  ValueDisplayed: 10µF  [1206_190]  (hidden comment: C1206C106K3RACAUTO)
C233  VDC_V: 25V  ValueDisplayed: 10µF  [1206_190]  (hidden comment: C1206C106K3RACAUTO)
C234  VDC_V: 25V  ValueDisplayed: 10µF  [1206_190]  (hidden comment: C1206C106K3RACAUTO)
C235  VDC_V: 25V  ValueDisplayed: 10µF  [1206_190]  (hidden comment: C1206C106K3RACAUTO)
C236  VDC_V: 25V  ValueDisplayed: 10µF  [1206_190]  (hidden comment: C1206C106K3RACAUTO)
C237  VDC_V: 25V  ValueDisplayed: 10µF  [1206_190]  (hidden comment: C1206C106K3RACAUTO)
C240  VDC_V: 25V  ValueDisplayed: 100µF  [SM_RADIAL_6.3BMM]  (hidden comment: EEH-ZA1E101XP)
C241  VDC_V: 25V  ValueDisplayed: 100µF  [SM_RADIAL_6.3BMM]  (hidden comment: EEH-ZA1E101XP)
D9  150080VS75000  value Bright Green  [WL-SMCW_Green_0805]
D10  150080VS75000  value Bright Green  [WL-SMCW_Green_0805]
D11  150080VS75000  value Bright Green  [WL-SMCW_Green_0805]
D12  150080VS75000  value Bright Green  [WL-SMCW_Green_0805]
D13  150080VS75000  value Bright Green  [WL-SMCW_Green_0805]
J6  PJ-037AH  [PJ-037AH]
J7  Fan Connector  [Fan Connector]  (value not drawn)
J8  Fan Connector  [Fan Connector]  (value not drawn)
J9  Fan Connector  [Fan Connector]  (value not drawn)
L9  value 30 ohm  [0805_HV]  (hidden comment: MPZ2012S300AT000)
R163  Value2: 0.125W  ValueDisplayed: 2k  [0805_HV]  (hidden comment: CRCW08054K70FKEA)
R164  Value2: 0.125W  ValueDisplayed: 2k  [0805_HV]  (hidden comment: CRCW08054K70FKEA)
R165  Value2: 0.125W  ValueDisplayed: 1k  [0805_HV]  (hidden comment: CRCW08052K00FKEAC)
R166  Value2: 0.125W  ValueDisplayed: 1k  [0805_HV]  (hidden comment: CRCW08051K00FKEA)
R167  Value2: 0.125W  ValueDisplayed: 348  [0805_HV]  (hidden comment: CRCW0805348RFKEA)
R168  Value2: DNF  ValueDisplayed: 0  [0805_HV]  (hidden comment: CRCW08050000Z0EA)
R169  Value2: 0.125W  ValueDisplayed: 5k  [0805_HV]  (hidden comment: CRCW08055K00FKTA)
R170  Value2: DNF  ValueDisplayed: 0  [0805_HV]  (hidden comment: CRCW08050000Z0EA)
S1  M2011SS1W01  [M2011SS1W01]
U34  MIC39100-3.3WS-TR  [TLV1117]
U35  S24SE12002PDFA  [S24SE12002NDFA]
U36  PTH08080WAH  [PTH08080WAH]
U37  S24DE150R3PDFA  [S24SE12002NDFA]

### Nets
12V_IN: C232.1 C233.1 C234.1 C235.1 C236.1 C237.1 J6.1 J7.2(+VCC_RED) J8.2(+VCC_RED) J9.2(+VCC_RED) R163.2 S1.2(COMMON)
+3.3V: C216.1 C217.1 R166.2 U34.3(OUT)
+5V: C214.1 C215.1 C218.1 R165.2 U34.1(IN) U36.3(VO)
+12V: C209.1 C210.1 C223.1 C224.1 C225.1 C240.1(+) C241.1(+) L9.1 R164.2 U35.6(+VOUT) U37.1(+VIN)
+15V: C219.1 C221.1 C222.1 R169.2 U37.6(+VOUT)
-15V: C226.2 C228.2 C229.2 D13.1(K) U37.4(-VOUT)
GND: C209.2 C210.2 C211.2 C212.2 C213.2 C214.2 C215.2 C216.2 C217.2 C218.2 C219.2 C221.2 C222.2 C223.2 C224.2 C225.2 C226.1 C228.1 C229.1 C240.2(-) C241.2(-) D10.1(K) D11.1(K) D12.1(K) R167.1 R170.2 U34.2(GND) U34.4(GND) U35.4(-VOUT) U36.2(GND) U37.2(-VIN) U37.5(Comm)
GND_IN: C206.2 C207.2 C208.2 C230.2(-) C232.2 C233.2 C234.2 C235.2 C236.2 C237.2 D9.1(K) J6.2 J7.1(GND_BLACK) J8.1(GND_BLACK) J9.1(GND_BLACK) R168.2 U35.2(-VIN)
NetC206_1: C206.1 C207.1 C208.1 C230.1(+) S1.3(NO) U35.1(+VIN)
NetC211_1: C211.1 C212.1 C213.1 L9.2 U36.1(VI)
NetD9_2: D9.2(A) R163.1
NetD10_2: D10.2(A) R164.1
NetD11_2: D11.2(A) R165.1
NetD12_2: D12.2(A) R166.1
NetD13_2: D13.2(A) R169.1
NetR167_2: R167.2 U36.4(VO_ADJUST)
NetR168_1: R168.1 U35.3(ON/OFF)
NetR170_1: R170.1 U37.3(ON/OFF)

Not connected (* = marked no-connect by the designer): J7 3(SENSE_YELLOW)* 4(CONTROL_BLUE)*; J8 3(SENSE_YELLOW)* 4(CONTROL_BLUE)*; J9 3(SENSE_YELLOW)* 4(CONTROL_BLUE)*; U35 5(TRIM); U36 5(~{INHIBIT})*

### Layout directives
net class PowerSupply: 12V_IN, +3.3V, +5V, +12V, +15V, -15V, GND, GND_IN

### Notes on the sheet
- (near J6) 12V DC , 2Amps
- First use S24SE12002PDFA
- Fan 4 Pin:
  1. GND  - Black
  2. VCC  - Red
  3. Sense -Yellow
  4. Control - Blue
- 30kW Vienna PFC
- Power Supply
- R9

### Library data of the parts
?#8 = Title Block C
C206 C207 = C2012X5R1H475K125AB: as C28 on sheet Vienna_PFC_GateDriver
C208 C213 C217 C218 C222 C225 C229 = C0805C104J5RACTU: as C21 on sheet Vienna_PFC_GateDriver
C209 C210 C214 C219 C223 C224 C226 = C3216X5R1E336M160AC: CAP, CERM, 33 µF, 25 V, +/- 20%, X5R, 1206; Manufacturer: TDK; Polarized: N; CompType: Capacitor; Value: 33uF; U/M: EA; Tolerance_%: 20; Value1: Unknown; TaMin_C: -55; TaMax_C: 85; Cap_Case: 1206; AEC Category: Q200
C211 C212 C215 C216 C221 C228 C232-C237 = C1206C106K3RACAUTO: as C34 on sheet Vienna_PFC_GateDriver
C230 = EEH-ZA1H101V: CAP, Polymer Hybrid, 100 µF, 50 V, +/- 20%, 30 ohm, 6.3x7.7 SMD; Manufacturer: Panasonic; Polarized: Y; CompType: Capacitor; Value: 100uF; U/M: EA; Cap_F: 0.0001; Tolerance_%: 20; Value1: 30 ohm; ESR_ohm: 30; IRMS_A: 2; TaMin_C: -55; TaMax_C: 105; AEC Category: Q200
C240 C241 = EEH-ZA1E101XP: CAP, Polymer Hybrid, 100 µF, 25 V, +/- 20%, 30 ohm, 6.3x7.7 SMD; Manufacturer: Panasonic; Polarized: Y; CompType: Capacitor; Value: 100uF; U/M: EA; Cap_F: 0.0001; Tolerance_%: 20; Value1: 30 ohm; ESR_ohm: 30; IRMS_A: 2; TaMin_C: -55; TaMax_C: 105; AEC Category: Q200
D9-D13 = 150080VS75000: LED, Bright Green, SMD; Manufacturer: Wurth Elektronik; SymbolCreator: Altium; Type: AlInGaP; Vf_V: 2; Value2: 2V; Io_A: 0.02; Vr_V: 5; Tjmax_C: 85; Power_TotalModule: 0.072; Value1: 0.072W; Angle: 140; U/M: EA
J6 = PJ-037AH: Power Jack, 2mm, R/A, TH; Manufacturer: CUI Inc.; SymbolCreator: Altium; Pitch_mm: 6; Gender: Male; Shrouded: N; Row_Count: 1
J7-J9 = Fan Connector: 4 Positions Header Connector 0.100" (2.54mm) Through Hole Tin; Manufacturer: TE Connectivity AMP Connectors
L9 = MPZ2012S300AT000: as L1 on sheet Vienna_PFC_GateDriver
R163 R164 = CRCW08054K70FKEA: RES, 4.7K, 1%, 0.125 W, 0805; Manufacturer: Vishay-Dale; CompType: Resistor; Value: 348; Tolerance_%: 1; Power_W: 0.125; VDC_V: 150; TempCo: 100 ppm/C; EIA_Code: E96; U/M: EA; AEC Category: Q200
R165 = CRCW08052K00FKEAC: RES, 2K, 1%, 0.125 W, 0805; Manufacturer: Vishay-Dale; CompType: Resistor; Value: 348; Tolerance_%: 1; Power_W: 0.125; VDC_V: 150; TempCo: 100 ppm/C; EIA_Code: E96; U/M: EA; AEC Category: Q200
R166 = CRCW08051K00FKEA: RES, 1 k, 1%, 0.125 W, 0805; Manufacturer: Vishay-Dale; CompType: Resistor; Value: 1k; Value_Code: 1kR; Tolerance_%: 1; Power_W: 0.125; VDC_V: 150; TempCo: 100 ppm/C; EIA_Code: E96; U/M: EA; AEC Category: Q200
R167 = CRCW0805348RFKEA: RES, 348, 1%, 0.125 W, 0805; Manufacturer: Vishay-Dale; CompType: Resistor; Value: 348; Value_Code: 348R; Tolerance_%: 1; Power_W: 0.125; VDC_V: 150; TempCo: 100 ppm/C; EIA_Code: E96; U/M: EA; AEC Category: Q200
R168 R170 = CRCW08050000Z0EA: as R5 on sheet Vienna_PFC_GateDriver
R169 = CRCW08055K00FKTA: RES, 5K, 1%, 0.125 W, 0805; Manufacturer: Vishay-Dale; CompType: Resistor; Tolerance_%: 1; Power_W: 0.125; VDC_V: 150; TempCo: 100 ppm/C; EIA_Code: E96; U/M: EA; AEC Category: Q200
S1 = M2011SS1W01: PartNumber: M2011SS1W01/CUL; Manufacturer: NKK Switches
U34 = MIC39100-3.3WS-TR: Linear Voltage Regulator IC  1 Output  1A SOT-223; Manufacturer: Microchip Technology
U35 = S24SE12002NDFA: DC/DC CONVERTER 12V 1.67A 6DIP; Manufacturer: Delta Electronics; CompType: DC DC Converters
U36 = PTH08080WAH: 2.25 A, 4.5 to 18 V Input Wide Adjust Miniature Power Module, -40 to 85 degC, 5-pin Module (EUF5), Pb-Free (RoHS); Manufacturer: Texas Instruments; Alternate PartNumber: Equivalent; Iout(Max)(A): 2.25; Regulated Outputs(#): 1; SubFamily: Non-Isolated POL; Vin(Max)(V): 18; Vin(Min)(V): 4.5; VO Adjustable: TRUE; Vout(Max)(V): 5.5; Vout(Min)(V): 0.9
U37 = S24DE150R3PDFA: DC/DC CONVERT +/-15V 330MA 6DIP; Manufacturer: Delta Electronics; CompType: DC DC Converters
